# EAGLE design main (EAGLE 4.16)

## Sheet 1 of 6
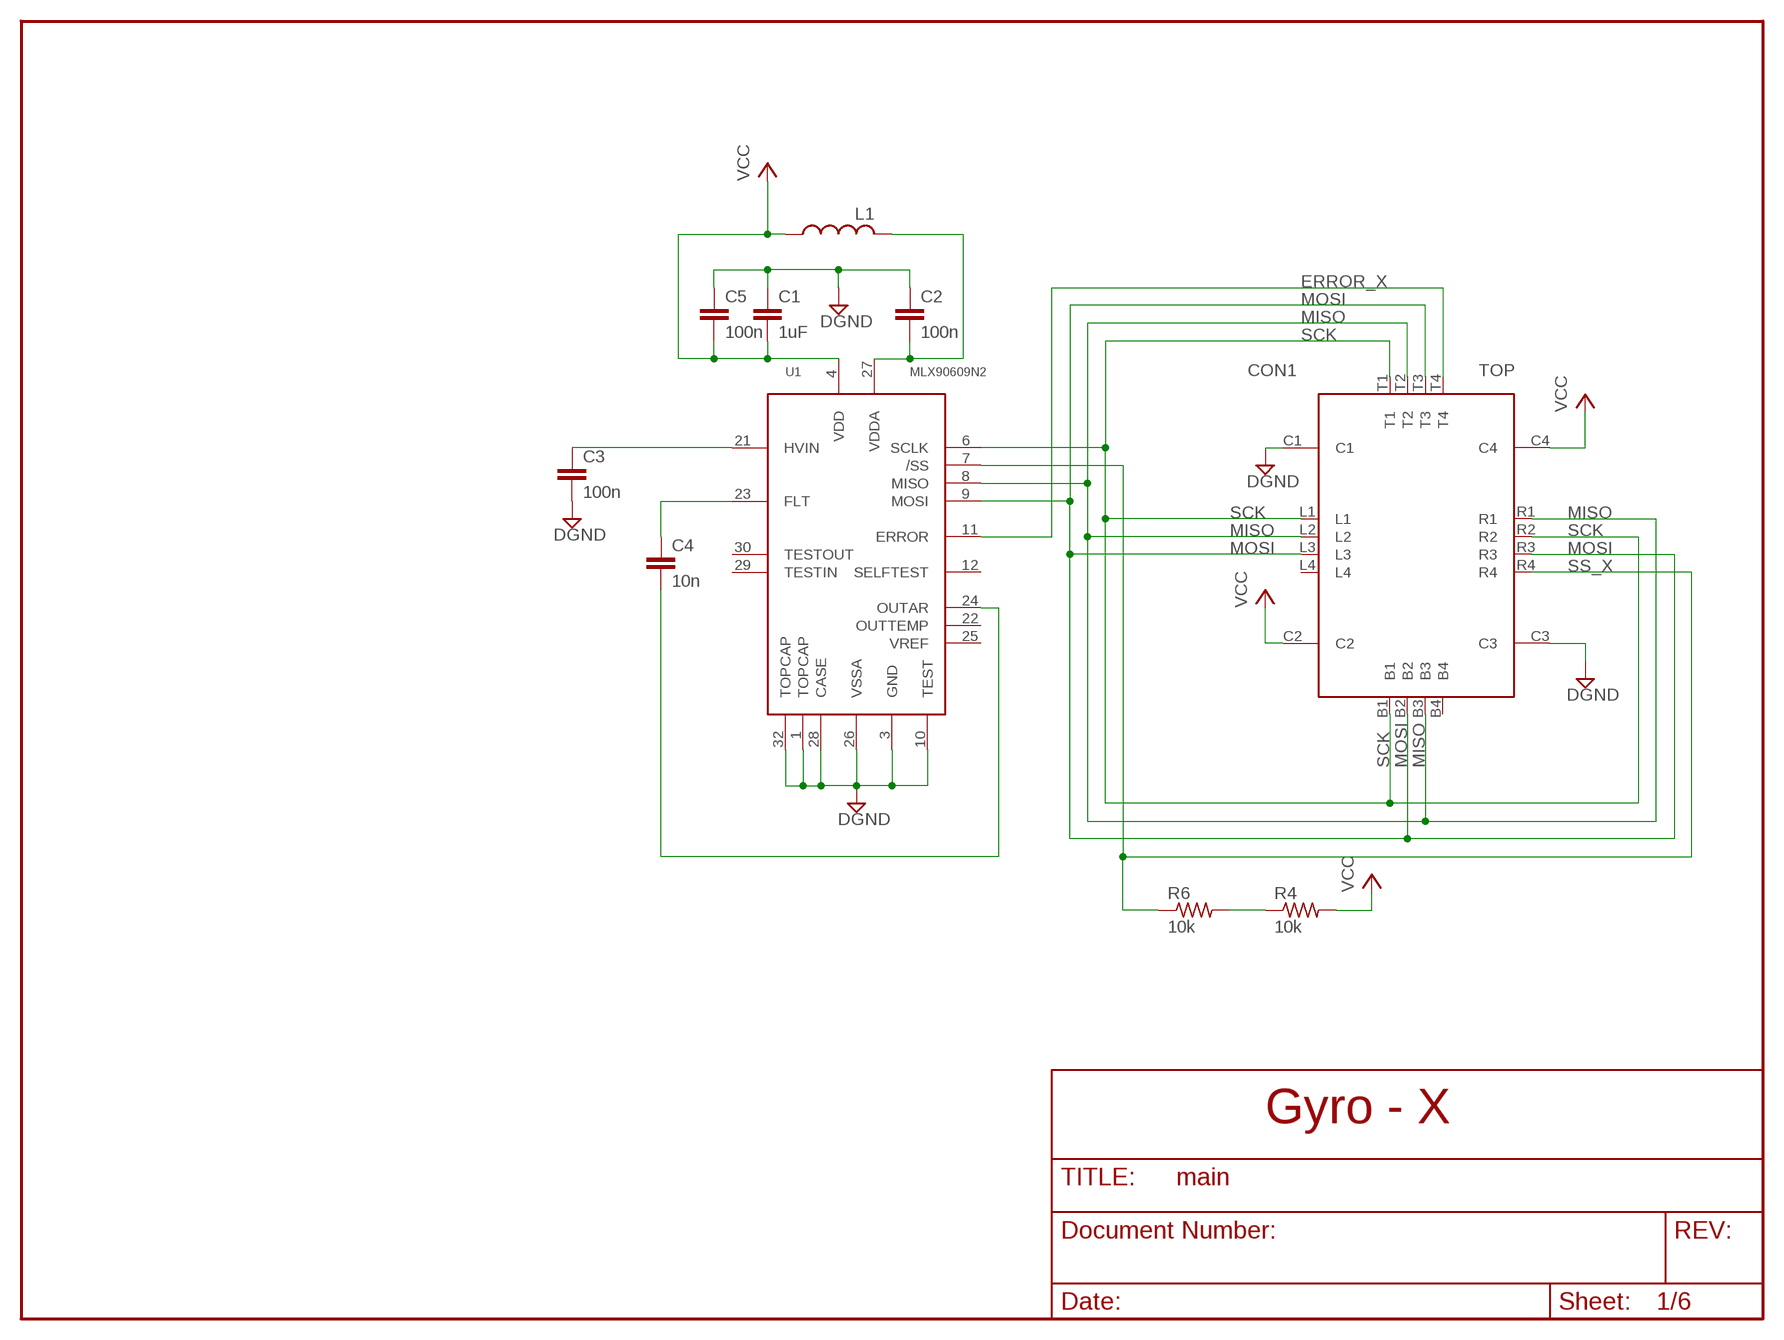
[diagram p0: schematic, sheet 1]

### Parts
C1  1uF  C-EUC0603  [C0603]
C2  100n  C-EUC0603  [C0603]
C3  100n  C-EUC0603  [C0603]
C4  10n  C-EUC0603  [C0603]
C5  100n  C-EUC0603  [C0603]
CON1  TOP  BOARDLEVEL  [BOARDLEVEL]
L1  L-USL2012C  [L2012C]
R4  10k  R-US_R0603  [R0603]
R6  10k  R-US_R0603  [R0603]
U1  MLX90609N2  [CLCC-32]

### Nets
DGND: C1.1 C2.1 C3.2 C5.1 CON1.C1 CON1.C3 U1.1(TOPCAP) U1.3(GND) U1.10(TEST) U1.26(VSSA) U1.28(CASE) U1.32(TOPCAP) ; also sheet 2,3,4,5,6
ERROR_X: CON1.T4 U1.11(ERROR) ; also sheet 4,5
MISO: CON1.B3 CON1.L2 CON1.R1 CON1.T2 U1.8(MISO) ; also sheet 2,3,4,5
MOSI: CON1.B2 CON1.L3 CON1.R3 CON1.T3 U1.9(MOSI) ; also sheet 2,3,4,5
N$3: C3.1 U1.21(HVIN)
N$4: C4.1 U1.23(FLT)
N$5: C4.2 U1.24(OUTAR)
N$11: R4.1 R6.2
N$14: C2.2 L1.2 U1.27(VDDA)
SCK: CON1.B1 CON1.L1 CON1.R2 CON1.T1 U1.6(SCLK) ; also sheet 2,3,4,5
SS_X: CON1.R4 R6.1 U1.7(/SS) ; also sheet 5
VCC: C1.2 C5.2 CON1.C2 CON1.C4 L1.1 R4.2 U1.4(VDD) ; also sheet 2,3,4,5,6
Unconnected: CON1.B4 CON1.L4 U1.12(SELFTEST) U1.22(OUTTEMP) U1.25(VREF) U1.29(TESTIN) U1.30(TESTOUT)

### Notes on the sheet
- Gyro - X

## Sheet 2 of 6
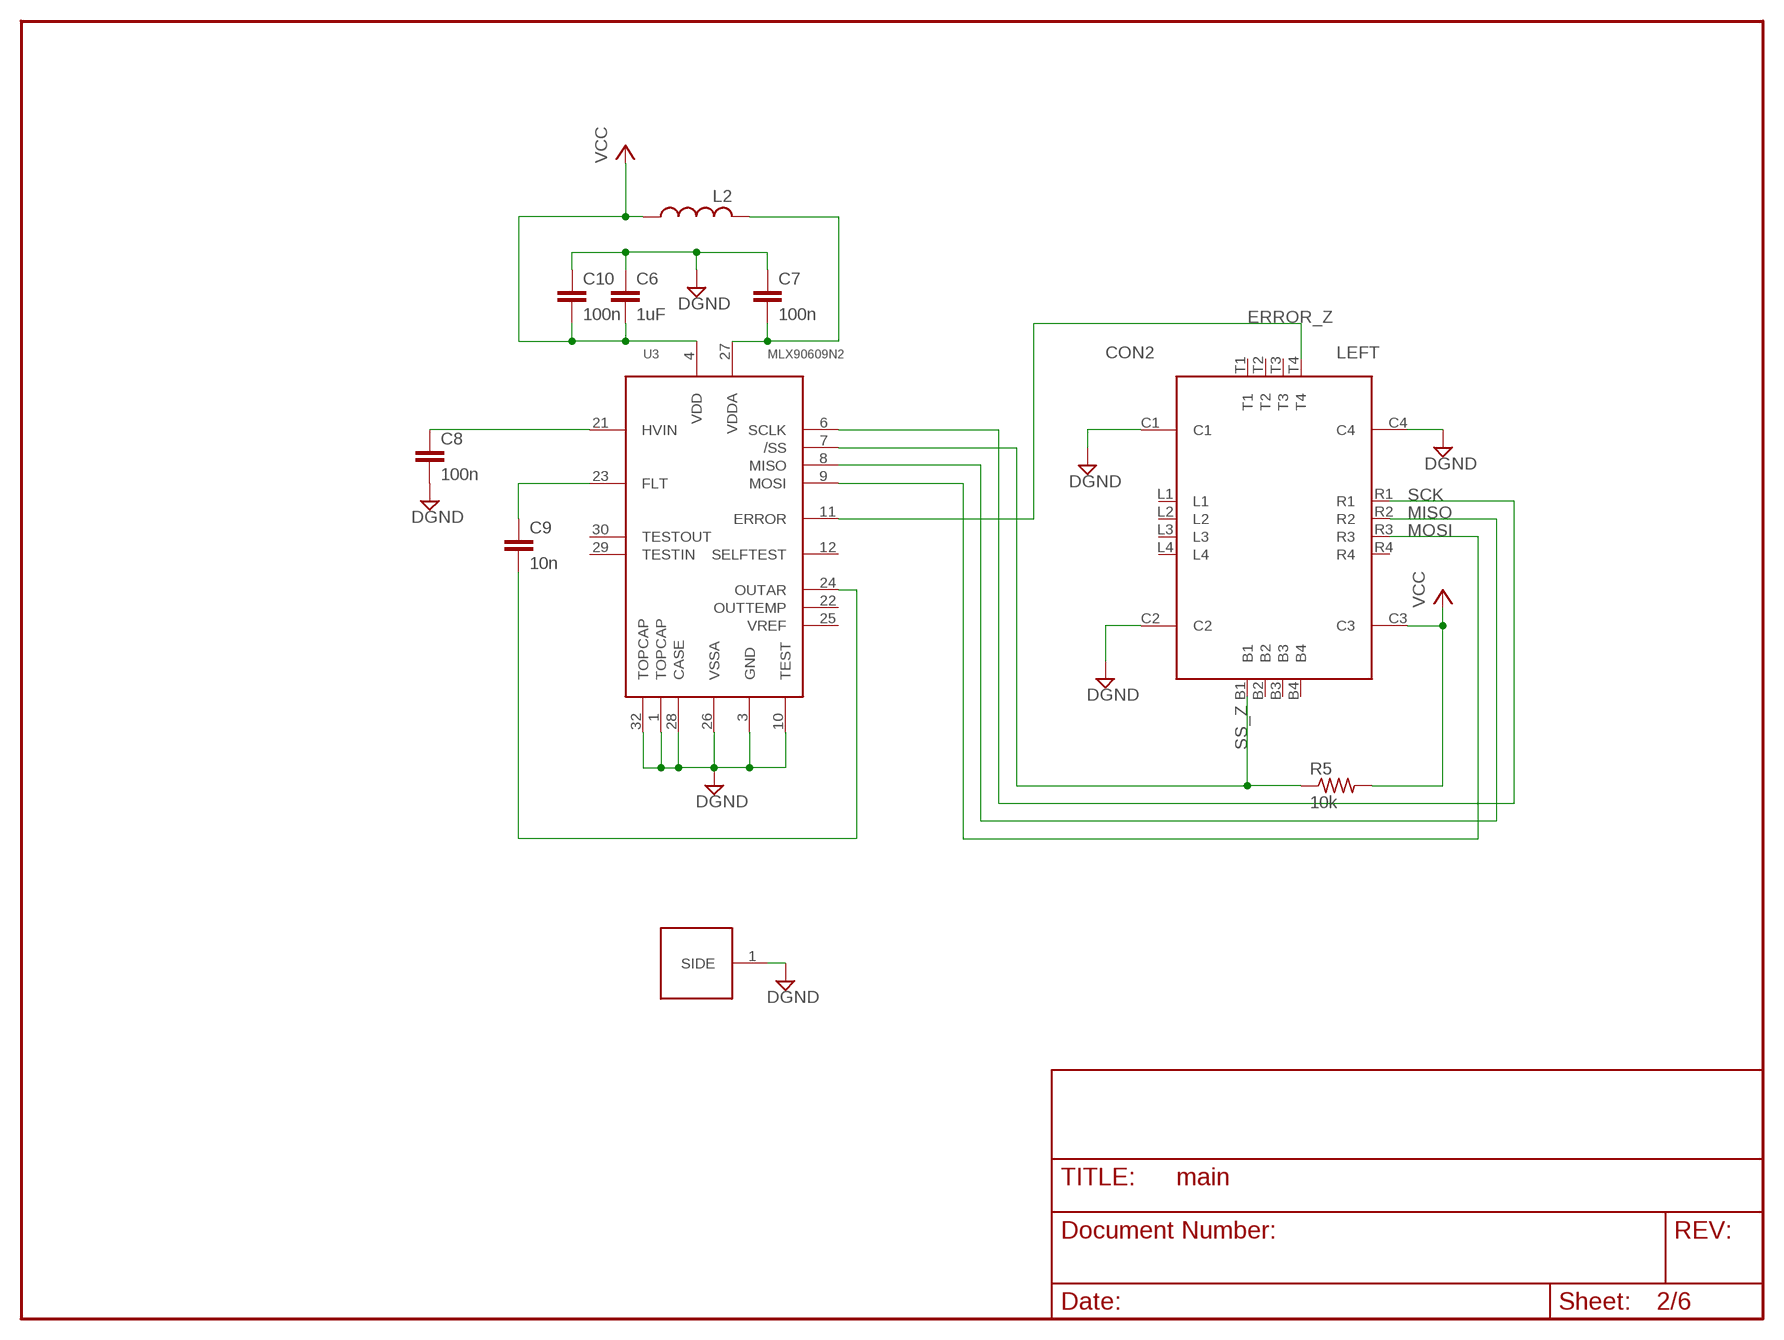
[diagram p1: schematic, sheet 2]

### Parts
C6  1uF  C-EUC0603  [C0603]
C7  100n  C-EUC0603  [C0603]
C8  100n  C-EUC0603  [C0603]
C9  10n  C-EUC0603  [C0603]
C10  100n  C-EUC0603  [C0603]
CON2  LEFT  BOARDLEVEL  [BOARDLEVEL]
L2  L-USL2012C  [L2012C]
R5  10k  R-US_R0603  [R0603]
U3  MLX90609N2  [CLCC-32]
U$1  1-SIDE  [1-SIDE]

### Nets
DGND: C6.1 C7.1 C8.2 C10.1 CON2.C1 CON2.C2 CON2.C4 U3.1(TOPCAP) U3.3(GND) U3.10(TEST) U3.26(VSSA) U3.28(CASE) U3.32(TOPCAP) U$1.1(SIDE) ; also sheet 1,3,4,5,6
ERROR_Z: CON2.T4 U3.11(ERROR) ; also sheet 4,5
MISO: CON2.R2 U3.8(MISO) ; also sheet 1,3,4,5
MOSI: CON2.R3 U3.9(MOSI) ; also sheet 1,3,4,5
N$12: C8.1 U3.21(HVIN)
N$13: C9.1 U3.23(FLT)
N$16: C9.2 U3.24(OUTAR)
N$54: C7.2 L2.2 U3.27(VDDA)
SCK: CON2.R1 U3.6(SCLK) ; also sheet 1,3,4,5
SS_Z: CON2.B1 R5.1 U3.7(/SS) ; also sheet 3,5
VCC: C6.2 C10.2 CON2.C3 L2.1 R5.2 U3.4(VDD) ; also sheet 1,3,4,5,6
Unconnected: CON2.B2 CON2.B3 CON2.B4 CON2.L1 CON2.L2 CON2.L3 CON2.L4 CON2.R4 CON2.T1 CON2.T2 CON2.T3 U3.12(SELFTEST) U3.22(OUTTEMP) U3.25(VREF) U3.29(TESTIN) U3.30(TESTOUT)

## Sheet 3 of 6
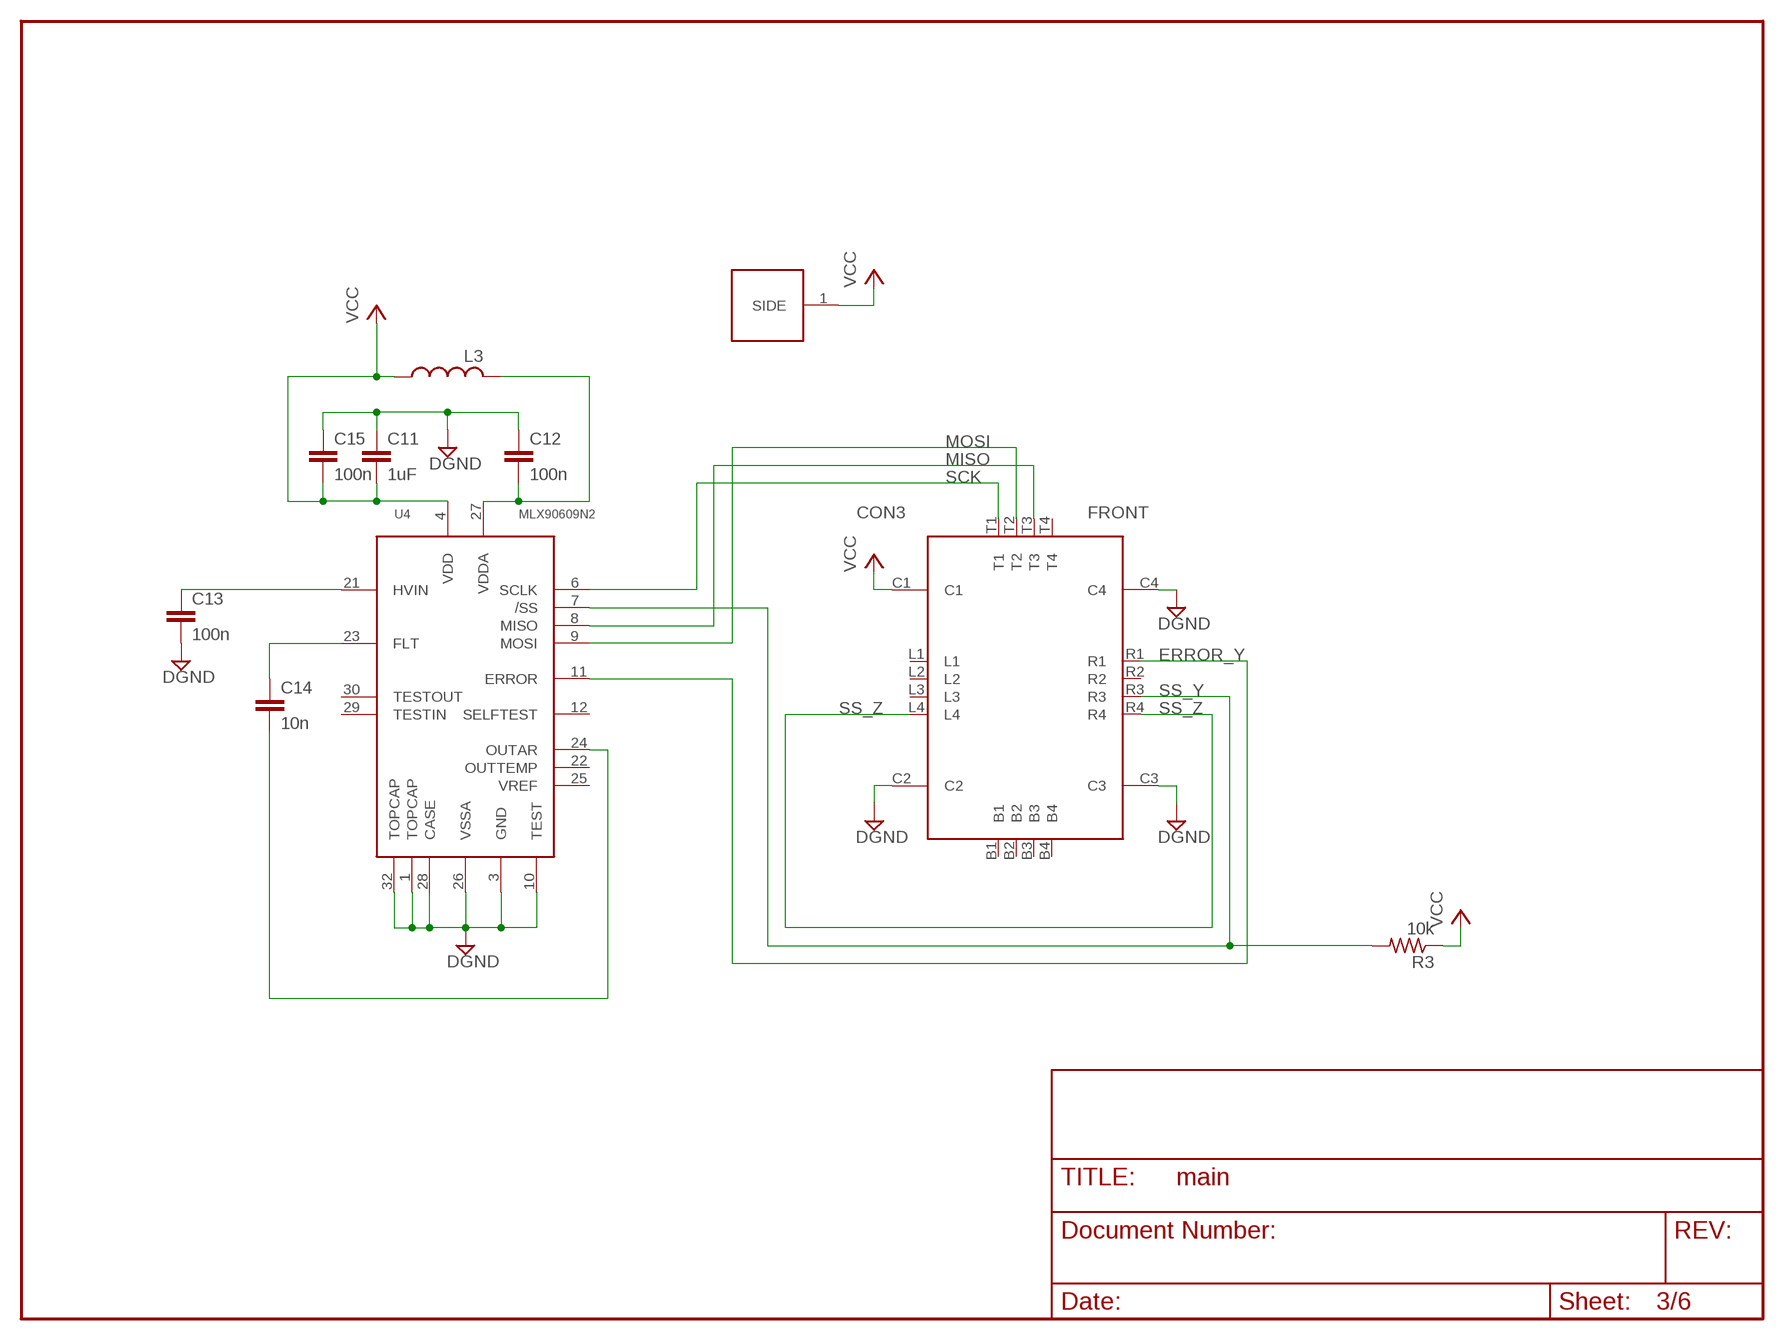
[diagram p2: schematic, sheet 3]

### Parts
C11  1uF  C-EUC0603  [C0603]
C12  100n  C-EUC0603  [C0603]
C13  100n  C-EUC0603  [C0603]
C14  10n  C-EUC0603  [C0603]
C15  100n  C-EUC0603  [C0603]
CON3  FRONT  BOARDLEVEL  [BOARDLEVEL]
L3  L-USL2012C  [L2012C]
R3  10k  R-US_R0603  [R0603]
U4  MLX90609N2  [CLCC-32]
U$4  1-SIDE  [1-SIDE]

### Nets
DGND: C11.1 C12.1 C13.2 C15.1 CON3.C2 CON3.C3 CON3.C4 U4.1(TOPCAP) U4.3(GND) U4.10(TEST) U4.26(VSSA) U4.28(CASE) U4.32(TOPCAP) ; also sheet 1,2,4,5,6
ERROR_Y: CON3.R1 U4.11(ERROR) ; also sheet 5
MISO: CON3.T3 U4.8(MISO) ; also sheet 1,2,4,5
MOSI: CON3.T2 U4.9(MOSI) ; also sheet 1,2,4,5
N$23: C13.1 U4.21(HVIN)
N$24: C14.1 U4.23(FLT)
N$26: C12.2 L3.2 U4.27(VDDA)
N$27: C14.2 U4.24(OUTAR)
SCK: CON3.T1 U4.6(SCLK) ; also sheet 1,2,4,5
SS_Y: CON3.R3 R3.2 U4.7(/SS) ; also sheet 5
SS_Z: CON3.L4 CON3.R4 ; also sheet 2,5
VCC: C11.2 C15.2 CON3.C1 L3.1 R3.1 U4.4(VDD) U$4.1(SIDE) ; also sheet 1,2,4,5,6
Unconnected: CON3.B1 CON3.B2 CON3.B3 CON3.B4 CON3.L1 CON3.L2 CON3.L3 CON3.R2 CON3.T4 U4.12(SELFTEST) U4.22(OUTTEMP) U4.25(VREF) U4.29(TESTIN) U4.30(TESTOUT)

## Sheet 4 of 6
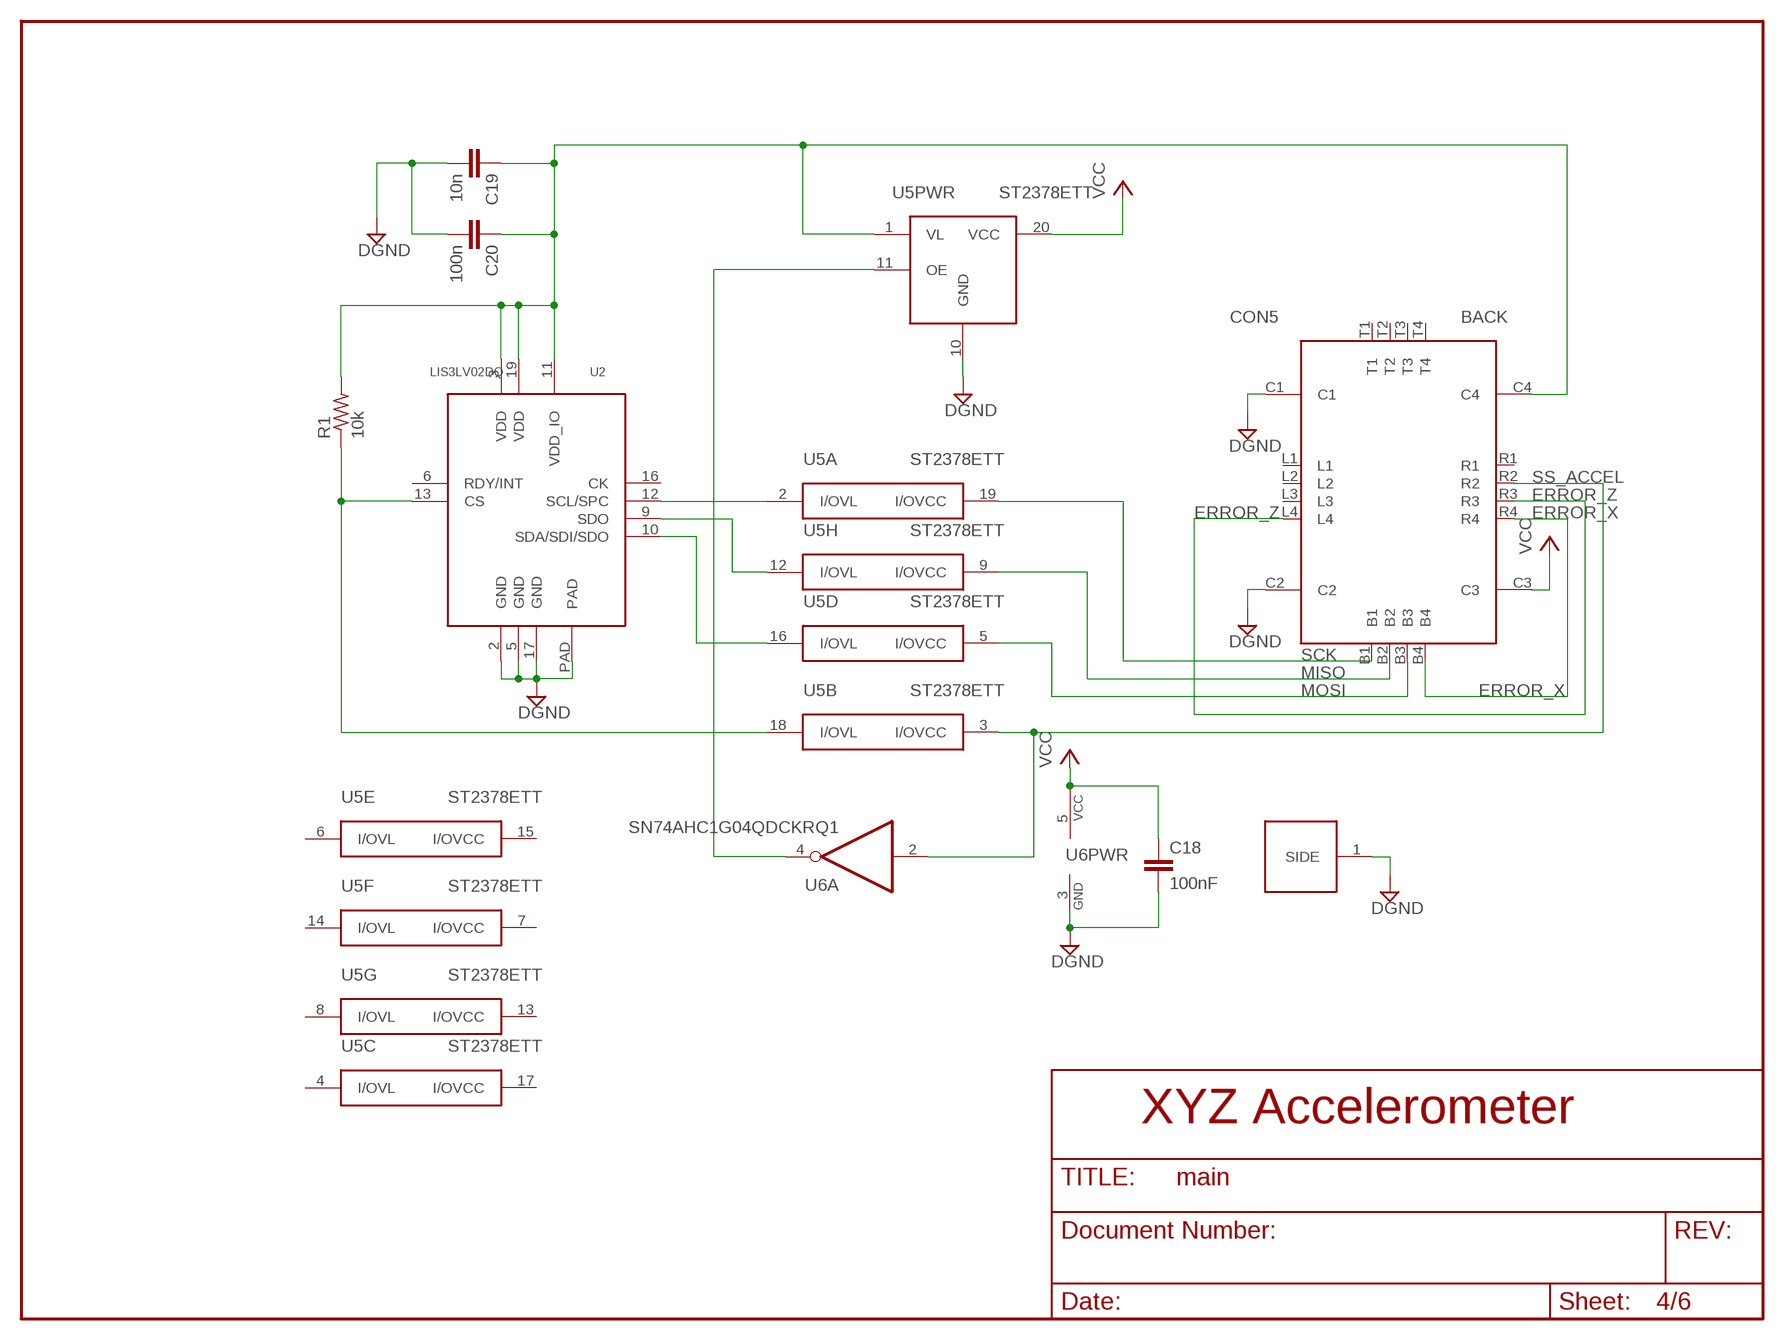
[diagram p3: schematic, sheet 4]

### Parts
C18  100nF  C-EUC0402  [C0402]
C19  10n  C-EUC0603  [C0603]
C20  100n  C-EUC0603  [C0603]
CON5  BACK  BOARDLEVEL  [BOARDLEVEL]
R1  10k  R-US_R0603  [R0603]
U2  LIS3LV02DQ  [QFPN-28]
U5  ST2378ETT  [TSSOP20]
U6  SN74AHC1G04QDCKRQ1  [SC70-5L]
U$3  1-SIDE  [1-SIDE]

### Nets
DGND: C18.2 C19.2 C20.2 CON5.C1 CON5.C2 U2.2(GND) U2.5(GND) U2.17(GND) U2.PAD U5.10(PWR:GND) U6.3(PWR:GND) U$3.1(SIDE) ; also sheet 1,2,3,5,6
ERROR_X: CON5.B4 CON5.R4 ; also sheet 1,5
ERROR_Z: CON5.L4 CON5.R3 ; also sheet 2,5
MISO: CON5.B2 U5.9(H:I/OVCC) ; also sheet 1,2,3,5
MOSI: CON5.B3 U5.5(D:I/OVCC) ; also sheet 1,2,3,5
N$8: U2.12(SCL/SPC) U5.2(A:I/OVL)
N$9: U2.10(SDA/SDI/SDO) U5.16(D:I/OVL)
N$10: U2.9(SDO) U5.12(H:I/OVL)
N$50: R1.1 U2.13(CS) U5.18(B:I/OVL)
N$53: U5.11(PWR:OE) U6.4(A:O)
SCK: CON5.B1 U5.19(A:I/OVCC) ; also sheet 1,2,3,5
SS_ACCEL: CON5.R2 U5.3(B:I/OVCC) U6.2(A:I) ; also sheet 5
VCC: C18.1 CON5.C3 U5.20(PWR:VCC) U6.5(PWR:VCC) ; also sheet 1,2,3,5,6
VCC2.5: C19.1 C20.1 CON5.C4 R1.2 U2.3(VDD) U2.11(VDD_IO) U2.19(VDD) U5.1(PWR:VL) ; also sheet 5
Unconnected: CON5.L1 CON5.L2 CON5.L3 CON5.R1 CON5.T1 CON5.T2 CON5.T3 CON5.T4 U2.6(RDY/INT) U2.16(CK) U5.4(C:I/OVL) U5.6(E:I/OVL) U5.7(F:I/OVCC) U5.8(G:I/OVL) U5.13(G:I/OVCC) U5.14(F:I/OVL) U5.15(E:I/OVCC) U5.17(C:I/OVCC)

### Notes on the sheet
- XYZ Accelerometer

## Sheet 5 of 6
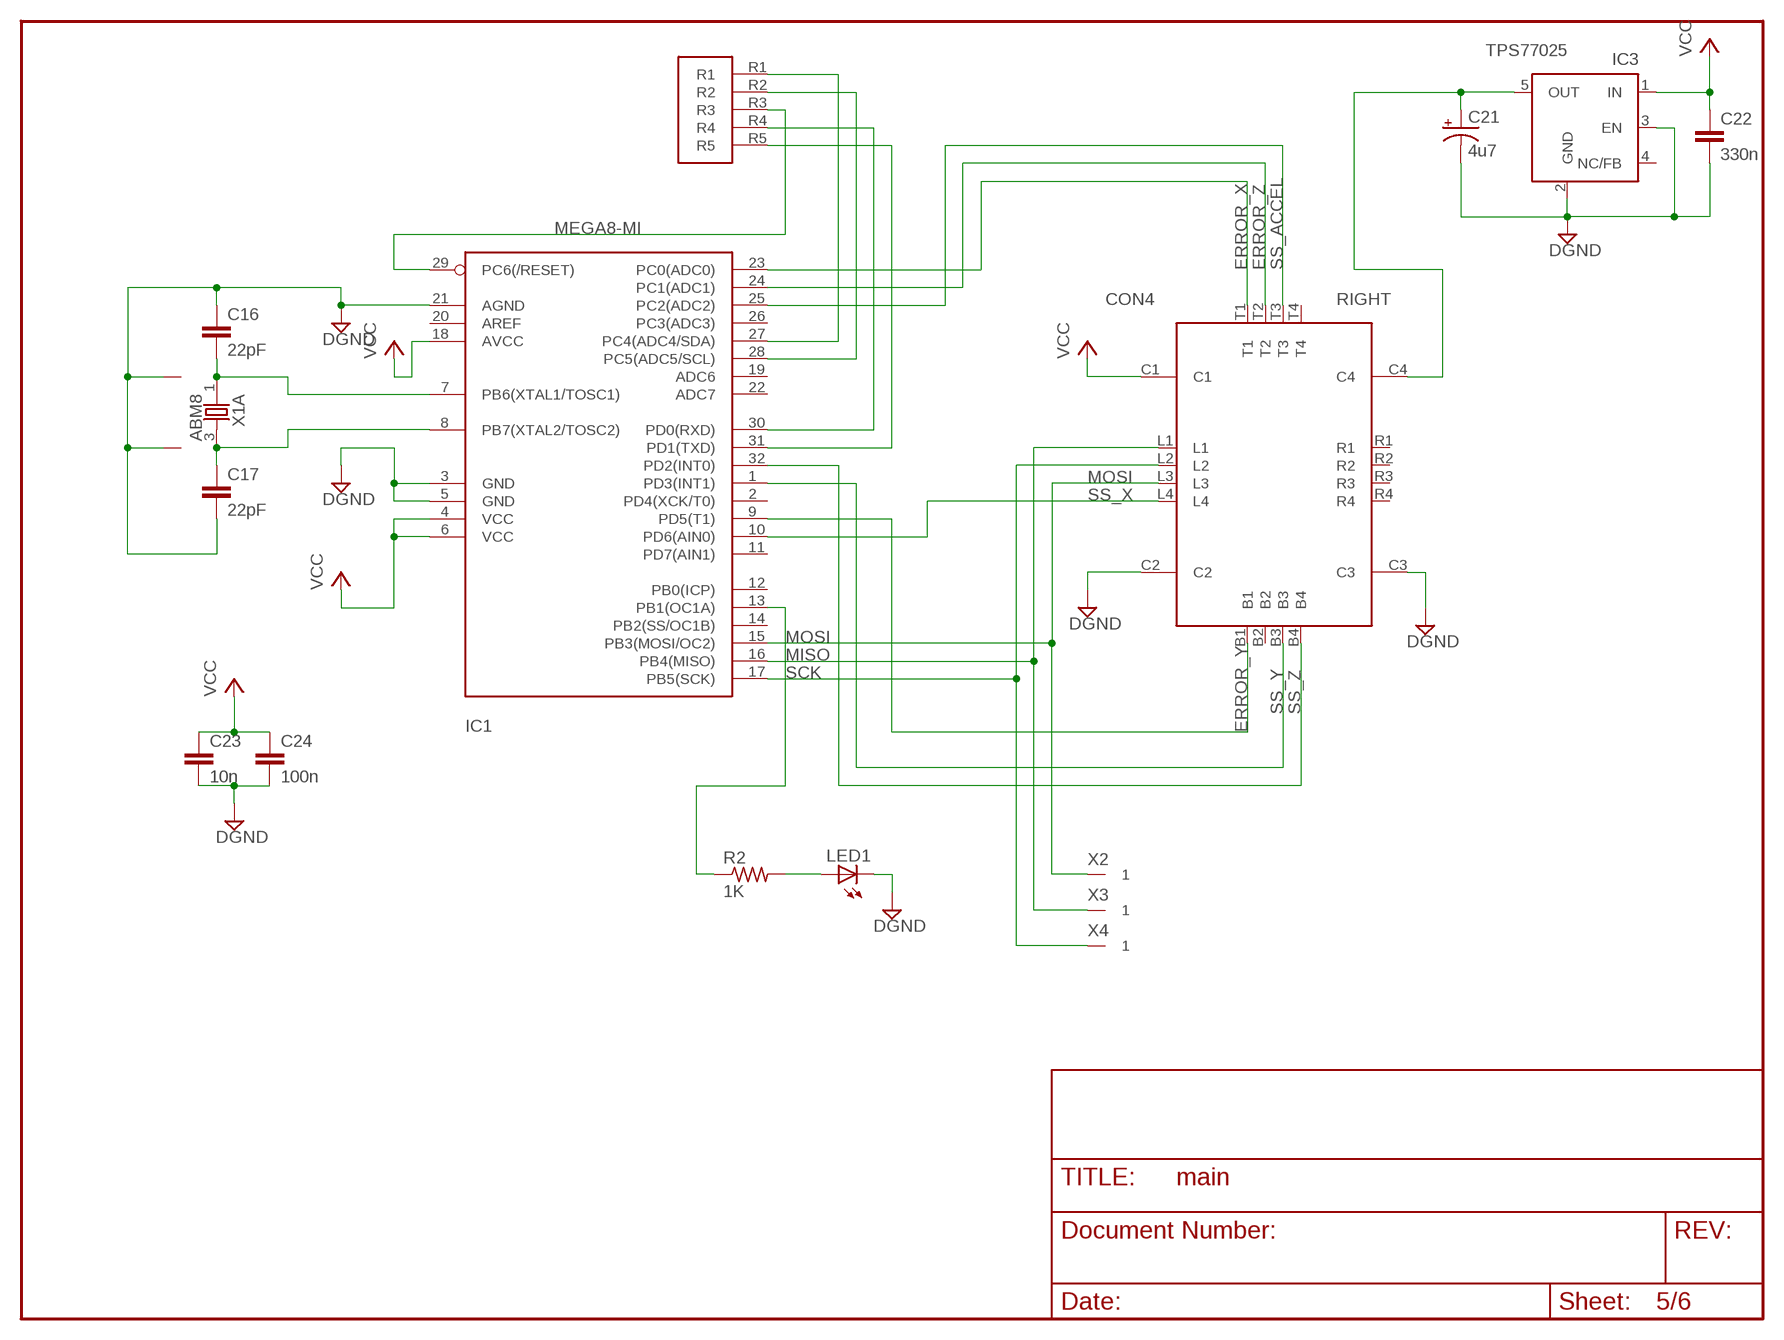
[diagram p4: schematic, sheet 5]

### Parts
C16  22pF  C-EUC0603  [C0603]
C17  22pF  C-EUC0603  [C0603]
C21  4u7  CPOL-USR/2012-12R  [R/2012-12R]
C22  330n  C-EUC0603  [C0603]
C23  10n  C-EUC0603  [C0603]
C24  100n  C-EUC0603  [C0603]
CON4  RIGHT  BOARDLEVEL  [BOARDLEVEL]
IC1  MEGA8-MI  [MLF32]
IC3  TPS77025  TPS770XX  [SOT23-5]
LED1  LEDCHIP-LED0805  [CHIP-LED0805]
R2  1K  R-US_R0603  [R0603]
U$2  5-RIGHT  [5-RIGHT]
X1  ABM8  [ABM8]
X2  ELLIPTICAL-PADS  [SMD-ELLIPSE]
X3  ELLIPTICAL-PADS  [SMD-ELLIPSE]
X4  ELLIPTICAL-PADS  [SMD-ELLIPSE]

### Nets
DGND: C16.1 C17.2 C21.- C22.2 C23.2 C24.2 CON4.C2 CON4.C3 IC1.3(GND) IC1.5(GND) IC1.21(AGND) IC3.2(GND) IC3.3(EN) LED1.C X1.2(GND) X1.4(GND) ; also sheet 1,2,3,4,6
ERROR_X: CON4.T1 IC1.23(PC0(ADC0)) ; also sheet 1,4
ERROR_Y: CON4.B1 IC1.9(PD5(T1)) ; also sheet 3
ERROR_Z: CON4.T2 IC1.24(PC1(ADC1)) ; also sheet 2,4
MISO: CON4.L1 IC1.16(PB4(MISO)) X3.1 ; also sheet 1,2,3,4
MOSI: CON4.L3 IC1.15(PB3(MOSI/OC2)) X2.1 ; also sheet 1,2,3,4
N$1: LED1.A R2.2
N$2: IC1.30(PD0(RXD)) U$2.R4
N$6: IC1.31(PD1(TXD)) U$2.R5
N$7: IC1.13(PB1(OC1A)) R2.1
N$15: IC1.29(PC6(/RESET)) U$2.R3
N$25: IC1.27(PC4(ADC4/SDA)) U$2.R1
N$56: IC1.28(PC5(ADC5/SCL)) U$2.R2
N$57: C16.2 IC1.7(PB6(XTAL1/TOSC1)) X1.1
N$58: C17.1 IC1.8(PB7(XTAL2/TOSC2)) X1.3
SCK: CON4.L2 IC1.17(PB5(SCK)) X4.1 ; also sheet 1,2,3,4
SS_ACCEL: CON4.T3 IC1.25(PC2(ADC2)) ; also sheet 4
SS_X: CON4.L4 IC1.10(PD6(AIN0)) ; also sheet 1
SS_Y: CON4.B3 IC1.1(PD3(INT1)) ; also sheet 3
SS_Z: CON4.B4 IC1.32(PD2(INT0)) ; also sheet 2,3
VCC: C22.1 C23.1 C24.1 CON4.C1 IC1.4(VCC) IC1.6(VCC) IC1.18(AVCC) IC3.1(IN) ; also sheet 1,2,3,4,6
VCC2.5: C21.+ CON4.C4 IC3.5(OUT) ; also sheet 4
Unconnected: CON4.B2 CON4.R1 CON4.R2 CON4.R3 CON4.R4 CON4.T4 IC1.2(PD4(XCK/T0)) IC1.11(PD7(AIN1)) IC1.12(PB0(ICP)) IC1.14(PB2(SS/OC1B)) IC1.19(ADC6) IC1.20(AREF) IC1.22(ADC7) IC1.26(PC3(ADC3)) IC3.4(NC/FB)

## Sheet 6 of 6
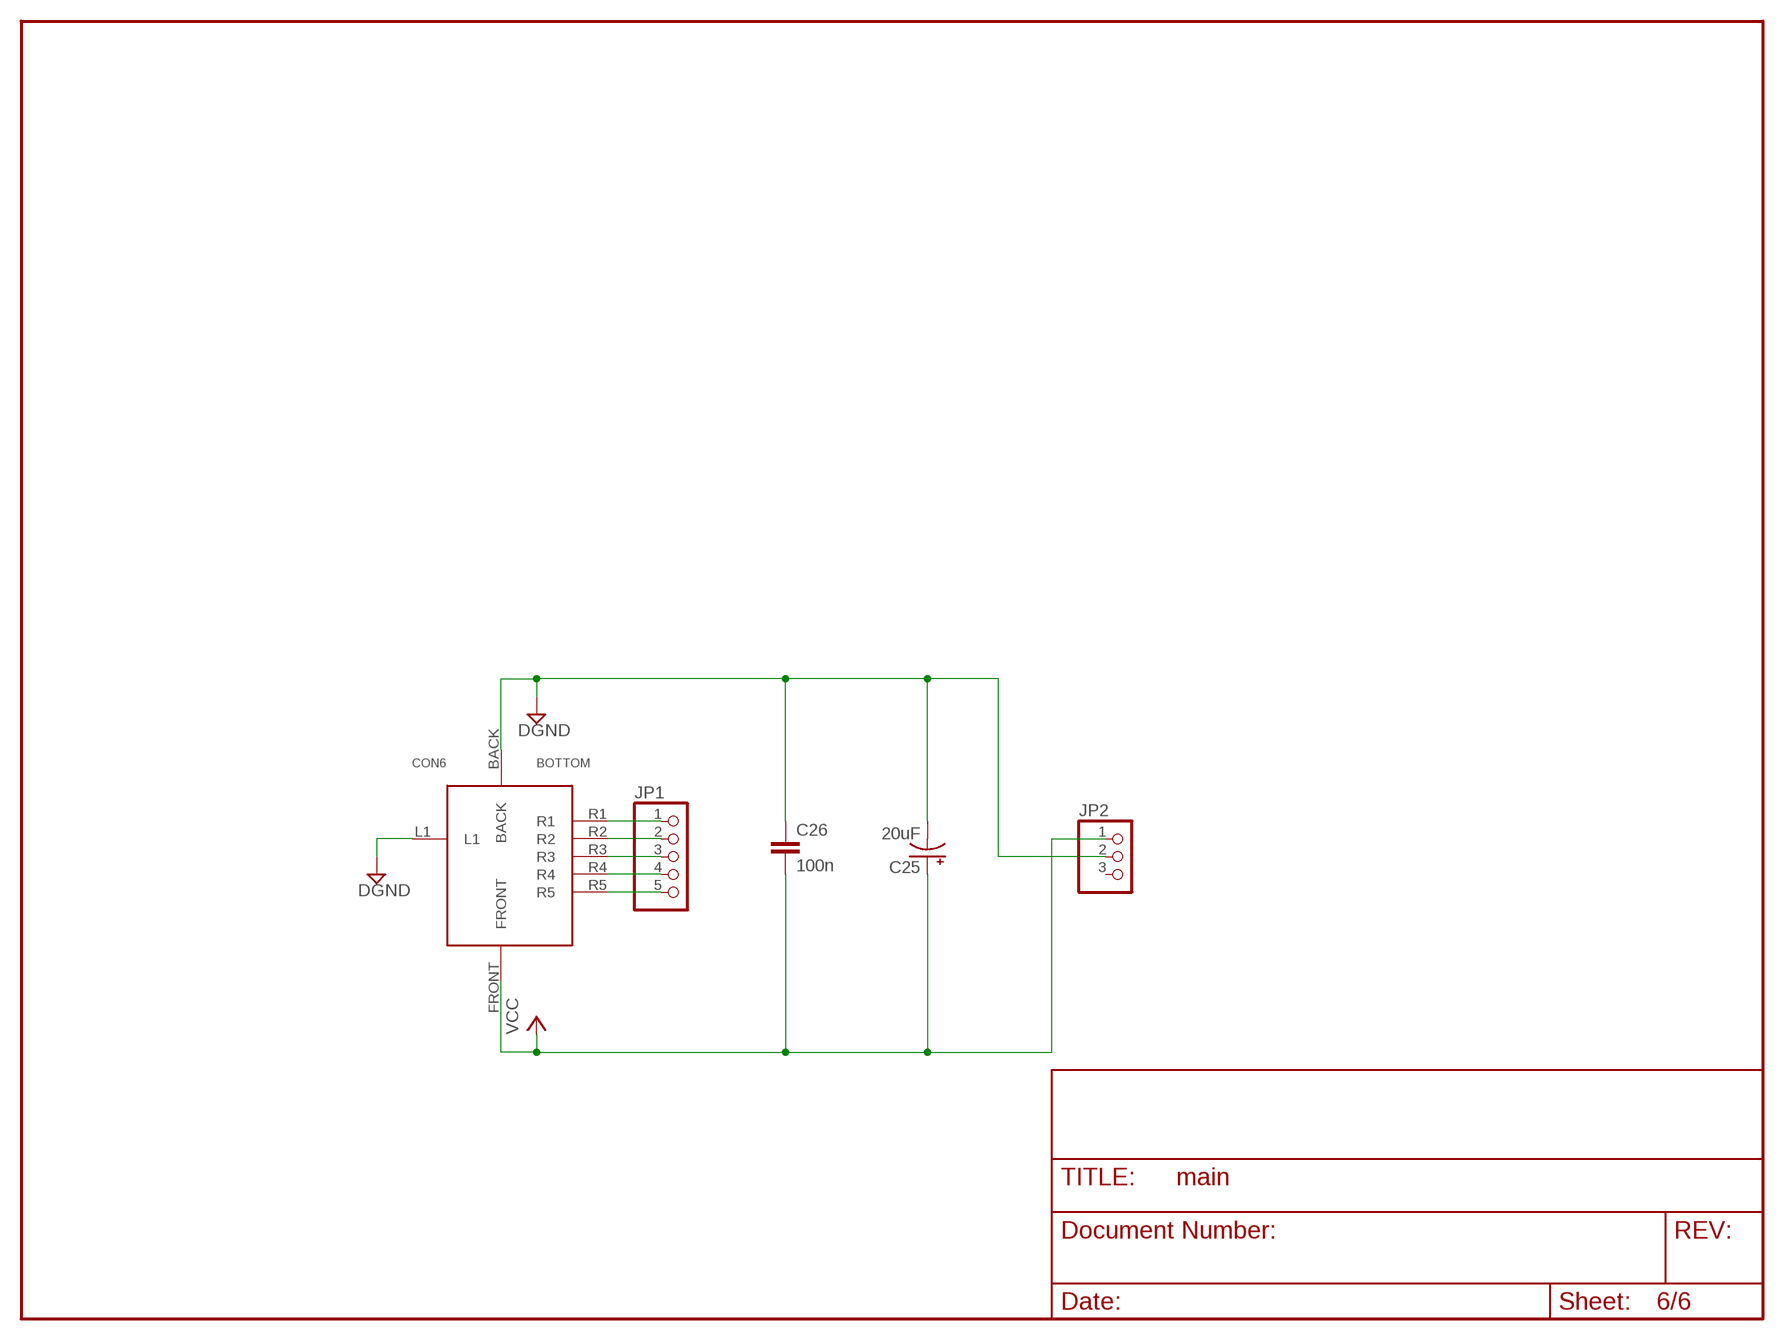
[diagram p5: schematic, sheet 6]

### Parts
C25  20uF  CPOL-USCT6032  [CT6032]
C26  100n  C-EUC0805  [C0805]
CON6  BOTTOM  [BOTTOM]
JP1  PINHD-1X5  [1X05]
JP2  PINHD-1X3  [1X03]

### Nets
DGND: C25.- C26.1 CON6.BACK CON6.L1 JP2.2 ; also sheet 1,2,3,4,5
N$61: CON6.R1 JP1.1
N$62: CON6.R2 JP1.2
N$63: CON6.R3 JP1.3
N$64: CON6.R4 JP1.4
N$65: CON6.R5 JP1.5
VCC: C25.+ C26.2 CON6.FRONT JP2.1 ; also sheet 1,2,3,4,5
Unconnected: JP2.3

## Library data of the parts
C1-C20 C22-C24 C26 = rcl:C-EU: CAPACITOR, European symbol
C21 C25 = rcl:CPOL-US: POLARIZED CAPACITOR, American symbol
CON1-CON5 = board-boardimu:BOARDLEVEL
CON6 = board-boardimu:BOTTOM
IC1 = atmel:MEGA8: MICROCONTROLLER 8 Kbytes FLASH 1 kbytes SRAM 512 bytes EEPROM USART 6-channel 10 bit ADC 2-channel 8 bit ADC Source: avr.lbr
IC3 = v-reg:TPS770XX: VOLTAGE REGULATOR
JP1 = pinhead:PINHD-1X5: PIN HEADER
JP2 = pinhead:PINHD-1X3: PIN HEADER
L1-L3 = rcl:L-US: INDUCTOR, American symbol
LED1 = led:LED: LED
R1-R6 = rcl:R-US_: RESISTOR, American symbol
U1 U3 U4 = melexis:MLX90609: Melexis Gyroscope
U2 = freescale:LIS3LV02DQ
U5 = st-microelectronics:ST2378E
U6 = 74xx-us:SN74AHC1G04QDCKRQ1
U$1 U$3 U$4 = board-boardimu:1-SIDE
U$2 = board-boardimu:5-RIGHT
X1 = crystal:ABM8
X2-X4 = special-pad:ELLIPTICAL-PAD

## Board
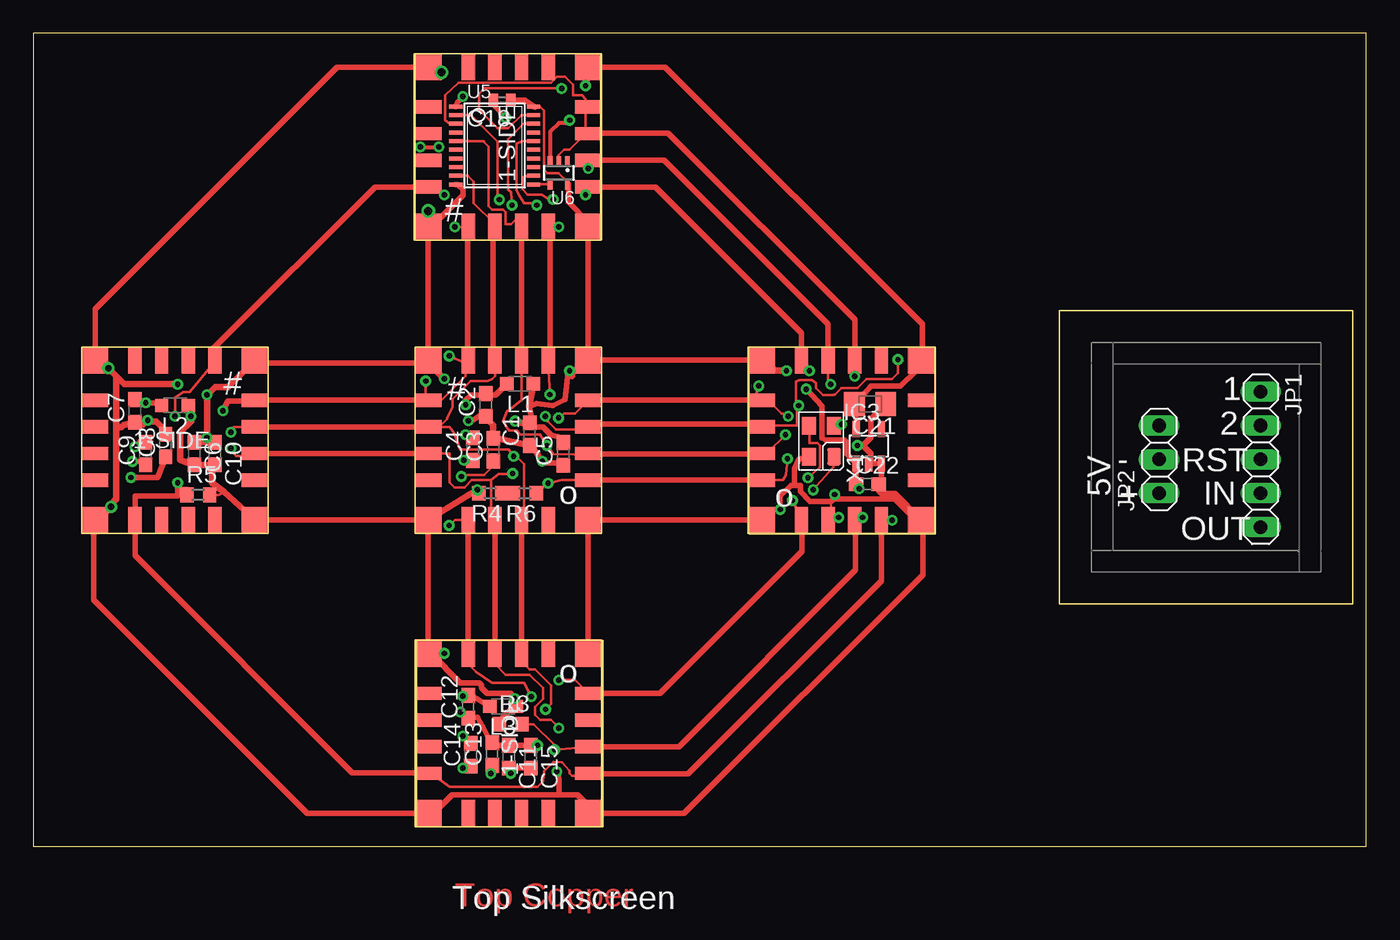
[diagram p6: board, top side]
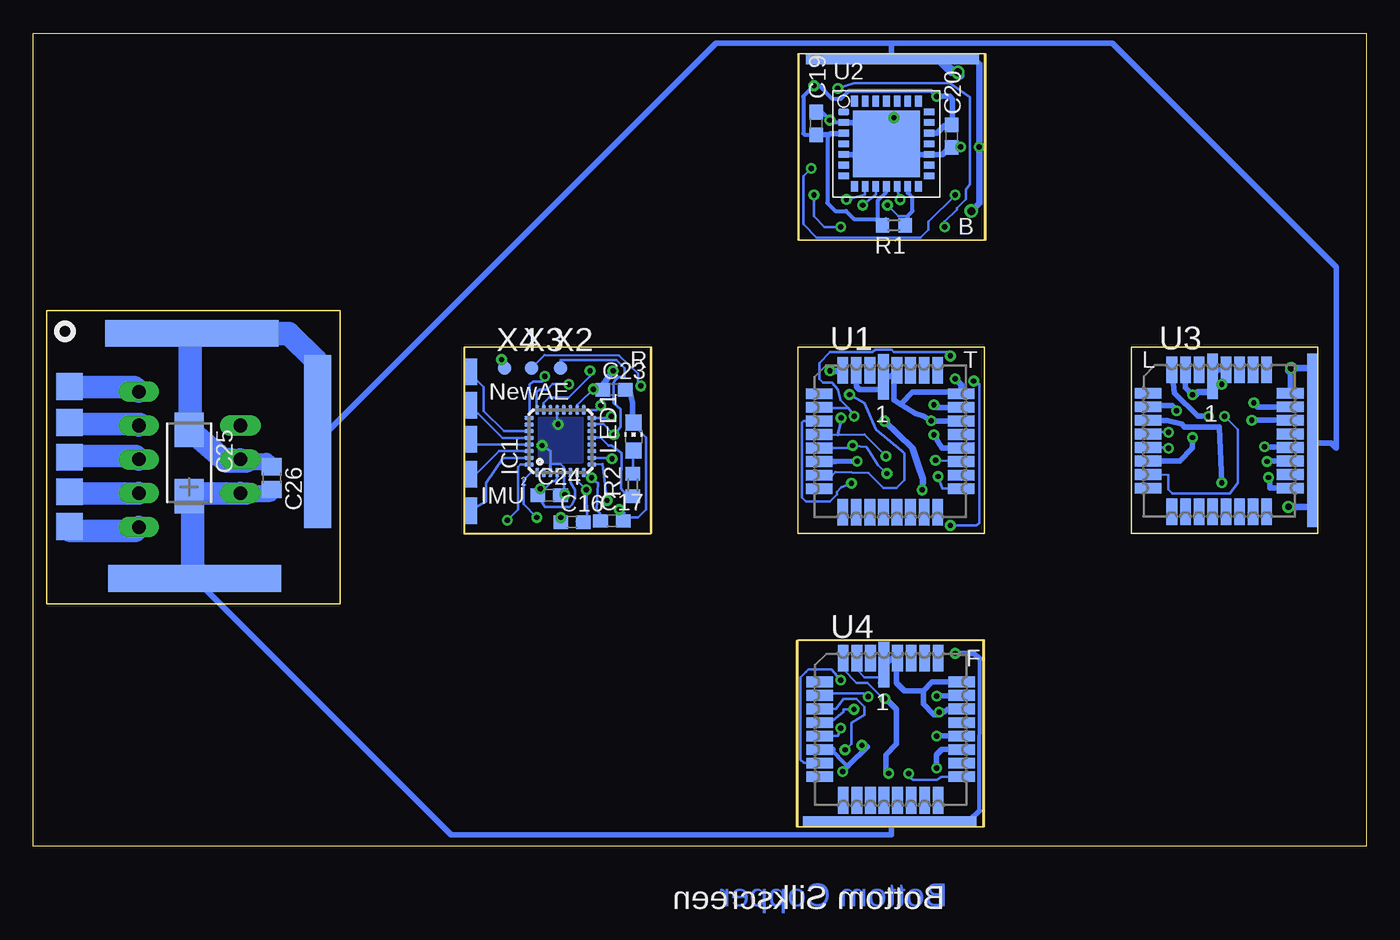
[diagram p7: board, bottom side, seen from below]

Size 100 x 61 mm. Coordinates in mm from the lower left corner, seen from the top.
Outline: 0,0 100,0 100,61 0,61 0,0
Copper layers (1*16): Top 0.035mm / dielectric 1.5mm / Bottom 0.035mm
Design rules "default": minimum track width 6mil, minimum drill 15mil, track to track 6mil, track to pad 6mil, pad to pad 6mil, via to via 6mil, smd to smd 0mil, copper to edge 0mil, drill to drill 6mil, minimum pad ring 10mil, minimum via ring 8mil, stop-mask expansion 4mil, vias tented up to drill 20mil, thermal gap 10mil

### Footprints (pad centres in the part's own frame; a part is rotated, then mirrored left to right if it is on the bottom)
C0603 = smd 1.1 x 1: 1 -0.85,0; 2 0.85,0
C0402 = smd 0.7 x 0.9: 1 -0.65,0; 2 0.65,0
R/2012-12R = smd 1.55 x 1.8: + 1.175,0; - -1.175,0
CT6032 = smd 2.6 x 2.2: + 2.5,0; - -2.5,0
C0805 = smd 1.3 x 1.5: 1 -0.85,0; 2 0.85,0
BOARDLEVEL = smd 1 x 2: B1 -3,-6; B2 -1,-6; B3 1,-6; B4 3,-6; T1 -3,6; T2 -1,6; T3 1,6; T4 3,6 | smd 2 x 2: C1 -6,6; C2 -6,-6; C3 6,-6; C4 6,6 | smd 2 x 1: L1 -6,3; L2 -6,1; L3 -6,-1; L4 -6,-3; R1 6,3; R2 6,1; R3 6,-1; R4 6,-3
BOTTOM = smd 13 x 2 bottom: BACK 0.1,9.3; FRONT -0.1,-9.1 | smd 2 x 13 bottom: L1 -9.315,1.17 | smd 2 x 2 bottom: R1 9.3,5.3; R2 9.3,2.6; R3 9.3,0; R4 9.3,-2.6; R5 9.3,-5.2
MLF32 = smd 0.7 x 0.3: 1 -2.35,1.75; 2 -2.35,1.25; 3 -2.35,0.75; 4 -2.35,0.25; 5 -2.35,-0.25; 6 -2.35,-0.75; 7 -2.35,-1.25; 8 -2.35,-1.75; 17 2.35,-1.75; 18 2.35,-1.25; 19 2.35,-0.75; 20 2.35,-0.25; 21 2.35,0.25; 22 2.35,0.75; 23 2.35,1.25; 24 2.35,1.75 | smd 0.3 x 0.7: 9 -1.75,-2.35; 10 -1.25,-2.35; 11 -0.75,-2.35; 12 -0.25,-2.35; 13 0.25,-2.35; 14 0.75,-2.35; 15 1.25,-2.35; 16 1.75,-2.35; 25 1.75,2.35; 26 1.25,2.35; 27 0.75,2.35; 28 0.25,2.35; 29 -0.25,2.35; 30 -0.75,2.35; 31 -1.25,2.35; 32 -1.75,2.35
SOT23-5 = smd 0.55 x 1.2: 1 -0.95,-1.3; 2 0,-1.3; 3 0.95,-1.3; 4 0.95,1.3; 5 -0.95,1.3
1X05 = drill 1.016 long: 1 -5.08,0; 2 -2.54,0; 3 0,0; 4 2.54,0; 5 5.08,0
1X03 = drill 1.016 long: 1 -2.54,0; 2 0,0; 3 2.54,0
L2012C = smd 1 x 1: 1 -1,0; 2 1,0
CHIP-LED0805 = smd 1.2 x 1.2: A 0,-1.05; C 0,1.05
R0603 = smd 1 x 1.1: 1 -0.85,0; 2 0.85,0
CLCC-32 = smd 0.8 x 3.4: 1 0,5.354 | smd 0.8 x 2: 2 -1.016,5.842; 3 -2.032,5.842; 4 -3.048,5.842; 13 -3.048,-4.826; 14 -2.032,-4.826; 15 -1.016,-4.826; 16 0,-4.826; 17 1.016,-4.826; 18 2.032,-4.826; 19 3.048,-4.826; 20 4.064,-4.826; 29 4.064,5.842; 30 3.048,5.842; 31 2.032,5.842; 32 1.016,5.842 | smd 2 x 0.8: 5 -4.826,4.064; 6 -4.826,3.048; 7 -4.826,2.032; 8 -4.826,1.016; 9 -4.826,0; 10 -4.826,-1.016; 11 -4.826,-2.032; 12 -4.826,-3.048; 21 5.842,-3.048; 22 5.842,-2.032; 23 5.842,-1.016; 24 5.842,0; 25 5.842,1.016; 26 5.842,2.032; 27 5.842,3.048; 28 5.842,4.064
QFPN-28 = smd 0.8 x 0.5: 1 -4.8,6.4; 2 -4.8,5.6; 3 -4.8,4.8; 4 -4.8,4; 5 -4.8,3.2; 6 -4.8,2.4; 7 -4.8,1.6; 15 1.6,1.6; 16 1.6,2.4; 17 1.6,3.2; 18 1.6,4; 19 1.6,4.8; 20 1.6,5.6; 21 1.6,6.4 | smd 0.5 x 0.8: 8 -4,0.8; 9 -3.2,0.8; 10 -2.4,0.8; 11 -1.6,0.8; 12 -0.8,0.8; 13 0,0.8; 14 0.8,0.8; 22 0.8,7.2; 23 0,7.2; 24 -0.8,7.2; 25 -1.6,7.2; 26 -2.4,7.2; 27 -3.2,7.2; 28 -4,7.2 | smd 5 x 5: PAD -1.6,4
TSSOP20 = smd 0.305 x 0.991: 1 -2.925,-2.918; 2 -2.275,-2.918; 3 -1.625,-2.918; 4 -0.975,-2.918; 5 -0.325,-2.918; 6 0.325,-2.918; 7 0.975,-2.918; 8 1.625,-2.918; 9 2.275,-2.918; 10 2.925,-2.918; 11 2.925,2.918; 12 2.275,2.918; 13 1.625,2.918; 14 0.975,2.918; 15 0.325,2.918; 16 -0.325,2.918; 17 -0.975,2.918; 18 -1.625,2.918; 19 -2.275,2.918; 20 -2.925,2.918
SC70-5L = smd 0.35 x 0.8: 1 -0.65,-0.85; 2 0,-0.85; 3 0.65,-0.85; 4 0.65,0.85; 5 -0.65,0.85
1-SIDE = smd 0.8 x 13 bottom: 1 -6.6,0
5-RIGHT = smd 1 x 2 bottom: R1 6.535,5.17; R2 6.535,2.64; R3 6.535,0.11; R4 6.535,-2.53; R5 6.535,-5.27
ABM8 = smd 1.321 x 1.041: 1 -2.311,0.432; 2 0,0.432; 3 0,2.311; 4 -2.311,2.311
SMD-ELLIPSE = smd 1 x 1: 1 0,0

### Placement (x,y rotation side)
C1  37.24,30.92 90 top
C2  33.95,33.12 90 top
C3  34.52,29.76 90 top
C4  32.98,29.79 90 top
C5  39.76,29.45 90 top
C6  12.08,29.47 270 top
C7  7.63,32.67 90 top
C8  9.93,30.07 90 top
C9  8.43,29.47 90 top
C10  13.63,29.47 270 top
C11  35.68,6.72 270 top
C12  32.63,10.47 90 top
C13  34.43,6.92 90 top
C14  32.83,6.87 90 top
C15  37.33,6.72 270 top
C16  59.58,24.32 0 bottom
C17  56.59,24.41 0 bottom
C18  35.17,56 180 top
C19  41.26,54.23 90 bottom
C20  31.11,53.28 270 bottom
C21  62.78,33.17 180 top
C22  62.58,27.17 0 top
C23  56.43,34.26 0 bottom
C24  61.3,26.33 0 bottom
C25  88.31,28.76 270 bottom
C26  82.11,27.62 270 bottom
CON1  35.63,30.47 0 top
CON2  10.63,30.47 0 top
CON3  35.63,8.47 0 top
CON4  60.63,30.47 0 top
CON5  35.63,52.47 0 top
CON6  87.99,29.2 0 top
IC1  60.45,30.39 90 bottom
IC3  62.68,30.02 0 top
JP1  92.09,29.03 270 top
JP2  84.47,29.03 90 top
L1  36.52,34.7 180 top
L2  10.63,33.07 180 top
L3  35.24,10.49 180 top
LED1  54.96,30.73 0 bottom
R1  35.44,46.6 180 bottom
R2  55.02,27.11 90 bottom
R3  35.82,9.16 0 top
R4  34.28,26.49 180 top
R5  12.38,26.36 0 top
R6  36.88,26.48 180 top
U1  36.22,29.88 0 bottom
U2  34.4,48.71 0 bottom
U3  11.53,29.92 0 bottom
U4  36.18,8.27 0 bottom
U5  34.61,52.58 270 top
U6  39.42,50.53 180 top
U$1  10.63,30.47 0 top
U$2  60.68,30.44 0 top
U$3  35.55,52.48 270 top
U$4  35.76,8.46 90 top
X1  60.51,31.55 90 top
X2  60.43,35.87 0 bottom
X3  62.63,35.87 0 bottom
X4  64.63,35.87 0 bottom

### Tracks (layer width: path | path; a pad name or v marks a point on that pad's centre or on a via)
DGND  (via drill 0.4, 0.5, 0.6)
  Top 0.2: X1.2 60.15,31.55 60.23,31.47 60.43,31.67 v60.63,31.67 | v60.43,24.67 59.83,25.27 59.83,25.87 | v60.12,26.39 60.04,26.47 60.03,26.47 60.03,26.07
  Top 0.3: C18.2 34.52,55.58 v35.43,54.67 | v29.03,52.47 v30.43,52.47 | U6.3 38.77,53.61 39.43,54.27 40.03,54.27 v40.24,54.48
  Top 0.4: C7.1 8.23,31.62 v8.58,31.97 | v5.63,35.87 5.23,35.87 CON2.C1 | v32.63,31.92 32.83,31.87 33.43,32.27 C2.1 | 66.63,24.57 66.53,24.57 64.63,26.47 63.63,26.47 63.43,26.67 C22.2 63.43,27.07 63.63,27.27 IC3.3 IC3.2 | IC3.2 | IC3.2 62.63,28.67 | X1.4 58.23,29.27 57.43,29.07 57.11,28.31 57.11,27.07 | CON4.C2 55.43,25.27 v56.03,25.27 56.03,26.27 56.83,27.07 57.11,27.07 | 57.11,27.07 57.57,27.07 57.57,26.61 58.26,25.87 58.98,25.86 58.99,25.87 59.83,25.87 60.03,26.07 64.63,26.07 66.23,24.47 66.83,24.47 | 62.23,30.07 v61.83,30.07 | 62.23,30.07 62.83,29.47 62.83,28.87 IC3.2 | IC3.2 | 60.03,31.27 60.08,31.32 X1.2 | C21.- 63.96,33.2 62.83,32.07 62.83,30.67 62.23,30.07 | 29.63,47.07 30.03,47.07 | U5.10 31.85,49.66 32.23,49.27 32.23,48.87 29.83,46.47 CON5.C2 | v37.83,7.57 C15.1 35.93,7.57 35.83,7.67 35.73,7.57 C11.1 34.53,7.57 34.43,7.67 | 34.43,7.67 34.28,7.92 33.72,9.01 33.33,9.67 32.63,9.67 C12.1 32.48,9.62 v32.03,10.07 | CON3.C2 30.03,2.47 31.43,3.87 39.43,3.87 | 39.43,3.87 40.83,3.87 41.43,3.27 41.43,2.67 CON3.C3 41.83,2.27 | 39.43,3.87 39.43,5.07 v39.28,5.6 | C1.1 37.83,29.47 38.23,28.77 | C5.1 39.77,28.47 39.74,28.53 39.23,28.77 38.23,28.77 | v38.18,28.89 37.81,29.44 38.23,28.77 | 34.43,7.67 C13.2
  Top 0.406: CON1.C1 CON5.C2 | 4.68,36.27 4.63,36.32 CON2.C1 4.63,40.32 22.78,58.47 CON5.C1 v30.63,58.07 | CON3.C3 48.83,2.47 66.73,20.37 66.73,24.47 66.63,24.57 CON4.C3 | 41.43,24.47 41.38,24.52 | 41.43,24.47 CON1.C3 CON4.C2 | CON3.C4 41.63,24.27 41.43,24.47 | CON2.C4 16.43,36.27 29.63,36.27 | CON3.C2 20.53,2.47 4.53,18.47 4.53,23.92 4.68,24.07 4.63,24.12 CON2.C2
  Top 0.5: 16.43,36.27 14.63,34.47 13.63,34.47 v13.03,33.87 v13.03,30.67 13.03,30.32 | C8.2 10.03,31.07 9.23,31.87 8.63,31.87 8.58,31.92 v8.58,31.97 | C10.1 13.68,30.32 13.63,30.27 13.58,30.32 13.03,30.32 | 13.03,30.32 C6.1 12.43,30.47 | CON2.C1 5.03,36.47 6.23,35.27 | 6.23,35.27 6.83,34.67 v10.83,34.67 | C7.1 6.78,31.62 6.63,31.47 6.43,31.47 6.23,31.27 | 6.23,31.27 6.23,35.27 | 4.83,24.47 6.23,26.07 6.23,31.27 | CON2.C2 4.83,24.47 | 4.83,24.47 v5.83,25.47 | CON1.C1 29.63,36.27 v30.83,35.07 | CON5.C2 29.63,47.07 v29.63,47.67 | C2.1 33.95,32.18 34.51,31.6 C3.2 34.83,30.59 C1.1
  Bottom 0.2: C24.2 60.21,26.65 60.23,26.67 60.2,26.7 IC1.5 60.23,28.07 60.23,28.47 60.43,28.67 61.23,28.67 61.23,28.07 IC1.3 61.2,29.64 v61.83,30.07 | v60.63,31.67 60.83,31.67 60.7,31.8 IC1.21 | 60.58,24.32 C16.1 v60.43,24.67 | C24.2 60.05,26.65 | U4.3 38.21,13.25 37.63,12.67 36.63,12.67 36.23,13.07 | 55.03,31.67 54.03,30.67 54.03,25.27 54.63,24.67 55.83,24.67 55.83,24.5 C17.2 | C24.2 60.43,26.31 60.43,26.27 60.24,26.27 v60.12,26.39
  Bottom 0.3: v35.43,54.67 35.43,53.27 36.03,52.67 | C19.2 40.84,55.08 v40.24,54.48 40.07,54.31 U2.2 | C20.2 30.47,52.43 v30.43,52.47 | 40.01,7.25 40.01,7.12 39.6,6.71 39.6,6.68 38.91,6 38.9,6
  Bottom 0.4: U3.26 5.71,31.95 5.73,31.97 v8.58,31.97 | U3.28 5.69,35.81 v5.63,35.87 | 11.63,35.27 | 11.63,35.27 U3.1 | U3.32 11.14,35.76 11.63,35.27 | U3.3 13.56,34.4 v13.03,33.87 12.83,33.87 | 11.63,34.67 11.63,35.27 | U1.10 39.82,28.86 v38.18,28.89 | U1.32 35.2,35.7 35.43,35.47 | 35.43,35.47 35.67,35.23 U1.1 36.22,35.08 36.23,35.07 36.23,34.47 36.43,34.27 38.03,34.27 38.25,34.49 U1.3 | 35.43,35.47 35.43,33.47 34.91,33.14 | 34.91,33.14 33.83,32.47 33.23,32.27 v32.63,31.92 32.59,31.91 U1.26 | C23.2 55.26,34.3 55.03,33.27 55.03,31.87 55.01,31.69 | 55.03,31.67 55.01,31.69 | 55.01,31.69 LED1.C | C17.2 55.74,24.98 v56.03,25.27 | C20.2 31.19,52.43 31.23,52.47 31.79,51.91 U2.17 33.99,51.91 34.23,51.67 35.03,51.67 36.03,52.67 | U2.5 36.99,51.91 36.19,52.71 U2.PAD 36.03,52.67 | U2.2 37.67,54.31 36.03,52.67 | 30.63,10.27 30.83,10.27 30.8,10.3 U4.26 30.6,10.3 30.63,10.27 | 30.63,10.27 31.43,10.27 31.63,10.07 v32.03,10.07 32.03,9.87 32.43,9.87 33.23,10.67 33.23,11.67 | U4.28 32.57,12.33 33.23,11.67 | 33.23,11.67 34.63,11.67 35.23,12.27 35.23,13.87 35.43,14.07 35.39,14.11 U4.32 35.59,14.11 36.18,13.52 | 36.18,13.52 36.23,13.47 | 36.18,13.52 U4.1 36.23,13.67 36.23,13.07 36.23,12.47 36.43,12.27 | 41.03,7.27 U4.10 40.01,7.25 | v39.28,5.6 38.9,6 38.83,6.07 37.43,7.47 37.63,7.47 37.83,7.67 v37.83,7.57 | 13.23,30.67 v13.03,30.67 13.03,29.87 14,28.9 U3.10 | U1.28 30.5,34.07 34.03,34.07 34.83,33.27 34.83,33.22 34.91,33.14 | CON6.L1 48.77,60.27 35.63,60.27 | 35.63,60.27 19.03,60.27 2.23,43.47 2.23,29.87 2.63,30.27 4.03,30.27 U$1.1 | U$3.1 35.63,59.16 35.63,60.27
  Bottom 0.406: 87.01,38.5 CON6.BACK | U$3.1 32.24,59.08 31.63,58.47 | v30.63,58.07 31.63,58.47 | 31.63,58.47 31.15,57.99
  Bottom 0.5: U$1.1 4.03,35.87 v5.63,35.87 5.83,35.67 | v5.83,25.47 4.03,25.47 | U1.28 30.38,34.62 v30.83,35.07 | v29.63,47.67 29.03,48.27 v29.03,52.47 29.03,58.67 29.43,59.07 34.43,59.07 34.63,59.27 | 11.63,34.67 11.62,34.67 v10.83,34.67 | 12.83,33.87 12.63,34.07 11.63,34.07 11.03,34.67 v10.83,34.67 | v10.83,34.67 10.63,34.67
  Bottom 0.6: v30.63,58.07 30.43,57.82 31.93,58.92 31.93,58.87
  Bottom 1.27: C26.1 82.51,28.87 84.63,28.87 JP2.2
  Bottom 1.676: C25.- 85.52,28.87 85.23,29.07 85.43,28.87 84.63,28.87 84.31,28.87 | 84.31,28.87 84.03,28.87 | 84.31,28.87 JP2.2
  Bottom 1.778: 88.23,31.18 88.23,31.07 | 88.23,31.18 C25.- | CON6.BACK 88.23,38.36 88.23,31.18 | CON6.L1 78.83,30.52 78.83,36.47 80.83,38.47 86.98,38.47 87.01,38.5
  pour Bottom (no thermals): 58.83,32.07 62.03,32.07 62.03,28.87 58.83,28.87
ERROR_X  (via drill 0.4)
  Top 0.2: CON4.T1 57.63,36.27 v58.23,35.67 | 38.75,46.81 39.09,46.81 v39.43,46.47 | v41.43,48.87 CON5.R4 | CON1.T4 38.63,36.27 v38.76,33.89
  Top 0.4: CON5.R4 41.43,49.47
  Top 0.406: 38.75,46.47 38.75,46.81 | 38.75,46.47 CON5.B4 | CON1.T4 38.75,36.47 38.75,46.47 | CON5.R4 46.68,49.47 57.63,38.52 57.63,36.67 57.58,36.62 57.63,36.57 CON4.T1
  Bottom 0.2: v58.23,35.67 58.23,35.27 59.83,33.67 61.3,33.67 61.72,33.25 61.72,32.71 61.7,32.69 | 61.7,32.69 61.67,32.66 | 61.7,32.69 IC1.23 | v39.43,46.47 40.63,46.47 41.43,47.27 v41.43,48.87 | U1.11 40.05,27.85 39.83,28.07 37.35,28 37.35,27.99 36.23,26.87 35.23,26.87 34.63,27.47 34.63,29.47 34.83,29.67 34.84,29.66 | 34.84,29.66 34.77,29.6 | 34.84,29.66 36.78,31.26 37.63,33.27 v38.76,33.89
ERROR_Y  (via drill 0.4)
  Top 0.2: CON4.B1 v56.96,25.95 | v39.43,12.47 40.63,12.47 CON3.R1
  Top 0.406: CON3.R1 47.03,11.47 57.68,22.12 57.68,24.32 57.53,24.47 | 57.53,24.47 57.48,24.52 | 57.53,24.47 CON4.B1
  Bottom 0.2: IC1.9 57.31,28.68 v56.96,25.95 | U4.11 42.2,6.24 42.43,6.47 42.43,12.67 | 42.43,12.67 42.03,13.07 | 42.43,12.67 42.43,12.68 41.85,13.27 40.12,13.27 v39.43,12.47
ERROR_Z  (via drill 0.4)
  Top 0.2: CON4.T2 59.63,34.87 v59.83,34.67 | CON5.L4 30.23,49.47 v30.83,48.87 | v41.63,50.87 CON5.R3 | 13.53,36.27 11.73,34.07 11.23,34.07 10.63,33.67 v10.63,32.27
  Top 0.406: CON5.R3 47.33,51.47 59.63,39.17 59.63,36.57 59.58,36.52 CON4.T2 | CON5.L4 25.63,49.47 13.53,37.37 13.53,36.27 13.88,35.92 13.88,36.27 13.63,36.52 CON2.T4
  Bottom 0.2: v59.83,34.67 61.03,34.67 61.43,34.27 62.03,34.27 62.23,34.07 62.23,32.67 62.2,32.7 IC1.24 | v30.83,48.87 32.83,46.87 32.83,46.27 33.43,45.67 41.23,45.67 42.23,46.67 42.23,50.27 v41.63,50.87 | U3.11 14.83,27.87 14.83,26.76 14.54,26.47 10.23,26.47 9.63,27.27 9.63,31.27 v10.63,32.27
MISO  (via drill 0.4)
  Top 0.2: CON1.L2 30.43,31.47 | 30.43,31.47 31.03,32.07 31.03,32.13 31.46,32.96 31.46,33.56 32.8,34.9 34.07,34.9 34.43,35.06 34.63,35.27 CON1.T2 | 30.43,31.47 31.23,31.47 31.58,30.99 32.03,29.76 35.64,29.76 v36.03,29.27 36.23,29.27 36.83,28.67 36.83,25.07 36.63,24.87 CON1.B3 | U5.9 32.6,50.3 33.03,49.87 33.03,48.27 34.63,46.67 CON5.B2 | v38.43,10.27 38.83,10.67 38.83,12.07 37.63,13.27 37.23,13.27 36.63,13.87 CON3.T3 | CON2.R2 15.03,31.47 v14.83,31.07 | CON1.R1 40.63,32.47 39.83,32.47 39.43,32.07 39.43,31.97 v39.4,32.14 | v54.42,34.54 54.23,33.87 CON4.L1 54.71,33.39 55.21,33.39 56.13,32.47 56.23,32.47 56.43,32.27 56.44,32.28 v56.62,32.28 v56.63,32.27
  Top 0.4: CON1.B3 CON3.T3 | CON1.R1 CON4.L1
  Top 0.406: 34.48,36.47 34.48,36.27 | CON1.T2 34.48,36.47 | CON5.B2 34.48,46.47 34.48,36.47 | CON1.L2 29.53,31.57 29.43,31.47 CON2.R2
  Bottom 0.2: v36.03,29.27 37.66,30.9 39.67,30.87 39.43,31.67 | IC1.16 56.76,32.14 v56.63,32.27 | X3.1 61.63,36.87 56.07,36.83 54.63,35.47 54.63,34.75 v54.42,34.54 | v38.43,10.27 39.23,10.27 39.23,10.07 40.23,9.27 41.23,9.27 41.21,9.29 U4.8 | 40.2,30.9 U1.8 39.63,30.87 39.43,31.67 | 39.43,31.67 v39.4,32.14 | U3.8 16.43,30.87 | U3.8 | v14.83,31.07 16.23,31.07 U3.8
MOSI  (via drill 0.4)
  Top 0.2: CON1.T3 36.43,36.27 36.63,36.07 36.63,33.47 35.63,32.67 35.56,32.65 35.26,31.89 35.51,31.46 35.71,31.19 36.28,31.19 36.52,30.9 38.01,30.9 v38.52,30.07 38.44,30.34 38.99,29.45 40.6,29.41 41.06,29.16 41.35,29.52 41.05,29.47 CON1.R3 | 54.63,29.57 55.13,29.57 v56.43,30.87 | U5.5 33.8,52.91 33.81,52.88 33.8,52.88 33.79,52.87 34.15,52.51 34.15,48.03 34.41,47.77 35.24,47.77 35.43,47.58 35.43,46.67 35.83,46.67 36.23,47.07 36.63,47.07 | 36.63,47.07 36.23,46.87 | CON5.B3 36.63,47.07 | CON1.L3 31.23,29.47 31.23,27.3 31.6,26.93 32.35,26.93 32.89,27.47 34.33,27.47 | 34.33,27.47 34.9,27.93 35.53,27.93 35.84,28.05 35.95,28 v35.96,27.97 | 34.33,27.47 34.33,25.06 CON1.B2 | v39.43,8.87 38.83,9.47 38.03,9.47 37.63,9.87 37.63,10.47 38.23,11.07 38.23,11.87 37.23,12.87 35.43,12.87 34.63,13.67 CON3.T2 | v14.83,29.87 14.83,29.67 15.23,29.27 16.43,29.27 CON2.R3
  Top 0.4: CON1.B2 CON3.T2
  Top 0.406: 36.63,36.37 CON1.T3 CON5.B3 | 16.63,29.37 16.53,29.27 | CON2.R3 16.63,29.37 | CON1.L3 16.73,29.47 16.63,29.37 | CON1.R3 42.48,29.47 42.53,29.42 54.18,29.42 54.48,29.72 54.63,29.57 CON4.L3
  Bottom 0.2: 37.33,29.75 36.63,28.6 v35.96,27.97 | 37.33,29.75 37.44,29.88 | IC1.15 58.06,31.64 58.03,31.67 57.23,31.67 v56.43,30.87 v56.43,30.88 55.96,31.47 55.96,32.79 56.44,33.23 56.45,33.24 56.46,33.24 56.46,34.8 56.4,34.86 56.35,34.97 56.04,35.2 55.7,35.2 55.63,35.27 55.63,35.87 56.23,36.47 60.43,36.47 X2.1 | U4.9 39.63,8.27 v39.43,8.87 | 37.33,29.75 37.35,29.75 37.5,29.97 38.4,30.03 v38.52,30.07 38.49,30.24 38.97,29.9 U1.9 | U3.9 14.88,29.92 v14.83,29.87
N$1
  Bottom 0.2: 55.02,29.86 55.01,29.85 LED1.A | R2.2 55.02,29.86 | 55.02,29.86 55.03,29.87
N$2
  Bottom 0.2: U$2.R4 67.07,27.71 67.03,27.67 65.06,29.64 IC1.30
N$3  (via drill 0.4)
  Top 0.2: C3.1 34.83,28.87 33.83,27.87 32.43,27.87 32.31,27.75 v32.12,27.75
  Bottom 0.2: U1.21 31.79,26.83 v32.12,27.75
N$4  (via drill 0.4)
  Top 0.2: C4.1 33.15,28.95 v32.31,28.96
  Bottom 0.2: U1.23 30.42,28.86 30.43,28.87 v32.31,28.96
N$5  (via drill 0.4)
  Top 0.4: C4.2 32.81,30.45 v32.43,30.87
  Bottom 0.4: v32.43,30.87 31.83,29.87 30.43,29.87 30.42,29.88 U1.24
N$6
  Bottom 0.2: IC1.31 64.76,29.14 66.03,27.27 66.03,25.87 67.41,25.08 | 67.41,25.08 67.43,25.07 | 67.41,25.08 U$2.R5
N$7
  Bottom 0.2: R2.1 55.42,26.26 55.89,26.86 55.87,29.51 56.63,30.07 56.83,30.07 57.43,30.67 58.23,30.67 58.2,30.64 IC1.13
N$8  (via drill 0.4)
  Top 0.2: U5.2 32.85,54.85 34.83,52.87 34.83,48.67 34.98,48.52 | 34.98,48.52 35.03,48.47 | v34.96,48.52 34.98,48.52
  Bottom 0.2: U2.12 35.2,49.3 v34.96,48.52
N$9  (via drill 0.4)
  Top 0.2: U5.16 36.66,52.91 36.24,52.72 36.25,49.24 36.43,48.84 36.81,48.26 37.35,48.26 37.78,48.03 | 37.78,48.03 37.81,48 | v37.78,48.11 37.78,48.03
  Bottom 0.2: U2.10 36.8,48.9 v37.78,48.11
N$10  (via drill 0.4)
  Top 0.2: 37.49,50.3 37.48,50.31 | 37.49,50.3 U5.12 | 37.49,50.3 37.5,50.29 36.84,50.29 36.71,50.16 36.71,49.29 37.07,48.89 38.13,48.88 38.61,48.6 38.7,48.6 38.83,48.47 38.89,48.53 v39,48.53
  Bottom 0.2: U2.9 37.6,48.9 v39,48.53
N$11
  Top 0.2: R6.2 35.84,26.48 35.83,26.47 35.81,26.49 R4.1
N$12  (via drill 0.4)
  Top 0.4: C8.1 9.33,27.67 v7.33,27.67
  Bottom 0.4: v7.33,27.67 7.43,27.47 7.23,27.67 7.23,26.87 5.83,26.87 U3.21
N$13  (via drill 0.4)
  Top 0.4: C9.1 8.63,28.67 8.43,28.87 v7.43,28.87
  Bottom 0.4: U3.23 7.4,28.9 v7.43,28.87
N$14  (via drill 0.4)
  Top 0.4: 33.85,33.87 33.83,33.87 | L1.2 34.69,33.87 33.85,33.87 | 33.85,33.87 C2.2 | 33.85,33.87 32.83,33.87 32.43,33.47 v32.43,33.13 32.43,33.07
  Bottom 0.4: U1.27 32.29,32.93 v32.43,33.13
N$15
  Bottom 0.2: 67.41,30.25 67.43,30.27 | 67.41,30.25 U$2.R3 | IC1.29 67.3,30.14 67.41,30.25
N$16  (via drill 0.4)
  Top 0.4: C9.2 7.98,30.32 v7.63,29.97
  Bottom 0.4: U3.24 5.78,29.92 5.83,29.97 v7.63,29.97
N$23  (via drill 0.4)
  Top 0.4: C13.1 34.63,5.67 v34.33,5.45
  Bottom 0.2: U4.21 31.88,5.22 32.22,4.97 34.02,4.97 34.43,5.27 v34.33,5.45
N$24  (via drill 0.4)
  Top 0.4: C14.1 32.63,5.67 32.83,5.87 v32.23,5.87
  Bottom 0.4: U4.23 31.85,7.25 32.23,6.87 v32.23,5.87
N$25
  Bottom 0.2: IC1.27 64.7,31.14 66.23,32.67 66.23,34.47 67.43,35.67 67.41,35.69 U$2.R1
N$26  (via drill 0.4)
  Top 0.4: L3.2 32.63,11.47 C12.2 32.28,11.32 v32.23,11.27
  Bottom 0.4: U4.27 30.38,11.32 30.43,11.27 v32.23,11.27
N$27  (via drill 0.4)
  Top 0.4: 32.83,7.67 C14.2 v32.23,8.27
  Bottom 0.4: U4.24 v32.23,8.27
N$50  (via drill 0.4)
  Top 0.2: v35.92,48.11 35.83,49.07 35.63,49.27 35.63,53.07 36.77,54.2 U5.18
  Bottom 0.2: 34.4,47.1 34.43,47.07 34.3,46.94 34.3,46.92 34.6,46.62 R1.1 | U2.13 34.34,49.57 34.3,49.53 | v35.92,48.11 35.08,47.27 34.43,47.27
  Bottom 0.3: U2.13 34.4,49.04 34.03,48.67 34.03,47.67 34.43,47.27 34.4,47.24 34.4,47.1
N$53
  Top 0.2: U5.11 37.62,49.66 37.64,49.68 U6.4
N$54  (via drill 0.4)
  Top 0.4: C7.2 7.63,33.27 v8.43,33.27 9.03,33.27 L2.2
  Bottom 0.4: U3.27 8.13,32.97 v8.43,33.27
N$56
  Bottom 0.2: IC1.28 64.8,30.64 66.63,32.47 66.83,32.47 67.41,33.05 | 67.41,33.05 67.43,33.07 | 67.41,33.05 U$2.R2
N$57  (via drill 0.4)
  Top 0.2: v58.51,26.74 58.75,27.03 60.03,28.47 60.03,28.87 60.23,29.07 60.08,29.22 X1.1
  Bottom 0.2: 59.22,28 59.2,28.02 IC1.7 | 59.22,28 59.2,27.98 | 59.22,28 59.22,27.46 v58.51,26.74 58.44,24.54 59.24,24.38 59.18,24.32 C16.2
N$58  (via drill 0.4)
  Top 0.2: v58.12,27.65 59.03,28.47 59.03,30.07 58.83,30.27 58.23,30.27 58.23,31.52 X1.3
  Bottom 0.2: IC1.8 58.66,28.04 58.63,28.07 v58.12,27.65 58.12,27.52 57.63,27.25 57.73,25.24 57.68,25.19 57.43,24.86 57.44,24.73 C17.1
N$61
  Bottom 1.676: CON6.R1 97.26,34.47 92.45,34.47 JP1.1
N$62
  Bottom 1.676: JP1.2 92.03,31.63 92.03,31.67 97.16,31.67 CON6.R2
N$63
  Bottom 1.676: 97.36,29.27 97.43,29.27 | 97.36,29.27 CON6.R3 | JP1.3 92.33,29.27 97.36,29.27
N$64
  Bottom 1.676: 97.42,26.47 97.43,26.47 | 97.42,26.47 CON6.R4 | JP1.4 92.11,26.47 97.42,26.47
N$65
  Bottom 1.676: CON6.R5 97.23,23.94 97.23,23.67 92.37,23.67 JP1.5
SCK  (via drill 0.4)
  Top 0.2: CON1.L1 30.43,33.47 | 32.43,36.27 32.63,36.07 | CON1.B1 31.63,24.47 v31.19,24.07 | v29.44,34.91 29.43,33.67 CON1.L1 | v64.87,36.52 64.87,35.51 64.43,35.07 62.51,35.06 61.83,34.38 60.64,34.39 60.14,33.89 60.05,33.89 60.03,33.87 59.23,33.87 58.7,34.4 58.7,34.77 58.41,35 57.47,35 57.23,34.86 | CON5.B1 v31.63,46.47 | 37.05,54.85 U5.19 37.45,54.85 37.43,54.87 36.63,54.87 35.63,53.87 34.83,53.87 33.43,55.27 33.43,56.47 33.83,56.87 v39.64,56.87 | 32.43,36.27 32.43,35.28 30.57,33.42 29.5,33.42 | 29.5,33.42 29.55,33.47 CON1.L1 | 29.5,33.42 29.44,33.36 | 32.43,36.27 v31.2,36.79 | 32.43,36.27 CON1.T1 | CON3.T1 32.63,13.67 33.23,13.07 34.43,12.27 36.83,12.27 v37.36,11.23 | 38.43,32.27 v38.41,32.26 v38.42,32.27 38.43,32.27 | CON1.R2 41.43,31.27 39.23,31.27 38.63,31.87 38.43,32.27 | 54.63,31.67 54.74,31.56 57.29,31.56 57.31,31.58 57.31,33.23 v57.43,33.07 57.23,33.27 57.23,34.86 | 57.23,34.86 57.23,34.87
  Top 0.4: 16.73,33.42 14.58,33.42 v14.23,32.67 | CON4.L2 54.63,31.67 41.83,31.67 CON1.R2
  Top 0.406: 32.58,36.47 32.58,36.17 | CON1.T1 32.58,36.47 | CON5.B1 32.58,46.47 32.58,36.47 | CON1.B1 32.53,24.37 32.63,24.27 CON3.T1 | CON2.R1 16.68,33.47 16.73,33.42 16.78,33.47 CON1.L1
  Bottom 0.2: 41.23,32.87 41.17,32.93 U1.6 | 41.23,32.87 41.03,32.87 41.05,32.89 U1.6 | v31.19,24.07 29.23,24.07 29.03,24.27 29.03,34.67 29.23,34.87 v29.44,34.91 | IC1.17 57.76,32.74 v57.43,33.07 | v64.87,36.52 X4.1 | v39.64,56.87 38.43,57.27 31.23,57.27 29.74,56.22 29.74,49.67 30.03,49.27 30.03,48.57 30.72,47.88 30.72,47.78 31.63,46.87 v31.63,46.47 | v31.2,36.79 31.22,36.8 31.23,36.87 31.43,37.07 35.43,37.07 35.63,37.27 36.83,37.27 37.03,37.07 40.23,37.07 41.03,36.27 41.03,35.07 40.74,34.78 40.1,34.78 39.63,34.27 39.43,33.47 38.83,32.87 | U4.6 40.88,11.32 40.83,11.27 40.63,11.47 37.61,11.46 37.38,11.23 v37.36,11.23 | 38.83,32.87 v38.41,32.26 | 41.23,32.87 U1.6 | 38.83,32.87 41.23,32.87
  Bottom 0.4: v14.23,32.67 14.53,33.07 16.23,33.07 16.33,32.97 U3.6
SS_ACCEL  (via drill 0.4)
  Top 0.2: CON4.T3 v61.63,35.27 | U6.2 39.42,51.86 39.83,52.27 40.23,52.27 41.43,53.47 | U5.3 31.23,54.2 30.91,54.47 30.91,56.37 31.89,57.3 38.84,57.3 39.28,57.74 39.9,57.74 40.51,57.13 40.51,56.35 41.15,56.35 41.43,56.07 41.43,53.67 CON5.R2 41.43,53.47 | 41.43,53.47 41.03,53.87
  Top 0.406: CON4.T3 61.63,39.52 47.63,53.52 41.58,53.52 41.53,53.47 | 41.53,53.47 41.48,53.42 | CON5.R2 41.53,53.47
  Bottom 0.2: v61.63,35.27 61.63,35.07 61.83,34.87 62.52,34.87 62.76,34.63 62.76,32.18 IC1.25
SS_X  (via drill 0.4)
  Top 0.2: v38.62,27.23 39.63,27.47 CON1.R4 | v56.58,29.07 56.48,27.85 56.23,27.47 CON4.L4 | v38.62,27.23 38.39,27.23 | 38.62,27.26 38.63,27.27 | 38.62,27.26 v38.62,27.23 | R6.1 37.84,26.48 38.62,27.26
  Top 0.406: CON1.R4 41.63,27.42 41.68,27.47 CON4.L4
  Bottom 0.2: U1.7 42.21,31.91 42.33,31.79 42.33,26.17 42.03,25.87 40.25,25.87 39.71,26.41 39.71,26.59 39.39,26.91 38.63,27.27 v38.62,27.23 | IC1.10 56.7,29.14 v56.58,29.07
SS_Y  (via drill 0.4)
  Top 0.2: v62.23,24.67 61.83,24.67 CON4.B3 | CON3.R3 v39.1,7.23 39.1,7.6 37.54,9.16 R3.2
  Top 0.406: CON3.R3 48.43,7.47 61.68,20.72 61.68,24.32 61.78,24.42 61.73,24.47 CON4.B3
  Bottom 0.2: IC1.1 62.66,28.04 63.23,27.47 63.23,25.67 v62.23,24.67 | U4.7 39.8,10.3 39.23,11.07 38.23,11.07 37.63,10.47 37.63,9.87 38.63,9.27 38.63,7.67 v39.1,7.23
SS_Z  (via drill 0.4)
  Top 0.2: 63.43,24.47 CON4.B4 v64.43,24.47 | 29.83,5.52 29.83,5.47 31.23,4.47 37.83,4.47 38.23,4.87 38.3,5.63 39.02,6.34 39.65,6.3 40.23,5.67 40.23,5.47 40.43,5.27 41.23,5.27 41.43,5.47 CON3.R4 | R5.1 11.62,26.27 11.63,26.27 11.63,26.87 10.83,26.87
  Top 0.4: CON2.B1 7.63,26.27 10.83,26.27 10.83,26.87 v10.83,27.27
  Top 0.406: CON4.B4 63.63,19.92 49.13,5.42 42.03,5.42 41.98,5.37 41.88,5.47 CON3.R4 | CON2.B1 7.63,21.82 23.93,5.52 29.83,5.52 29.78,5.47 CON3.L4
  Bottom 0.2: IC1.32 63.46,28.64 63.63,28.47 63.63,25.27 v64.43,24.47
  Bottom 0.4: U3.7 14.91,31.95 13.83,31.67 13.63,31.47 11.03,31.47 v10.83,27.27
VCC  (via drill 0.4)
  Top 0.2: 61.83,26.67 C22.1 61.83,27.07 v61.97,26.83 | U5.20 38.04,55.5 38.33,55.21 38.33,50.76 38.57,50.52 39.41,50.52 40.07,49.86 U6.5 | R4.2 33.43,26.47 33.31,26.59 v33.31,26.74 | R5.2 13.92,26.36 14.33,26.57
  Top 0.4: L2.1 11.63,32.47 v11.83,32.27 | v61.97,26.83 C22.1 IC3.1 61.03,29.42 61.03,30.27 60.83,30.47 59.43,30.47 59.15,30.65 59.15,33.05 58.03,34.27 57.92,34.47 v57.99,34.3 | CON4.C1 54.83,36.47 | 41.63,46.57 41.63,46.85 40.14,48.34 40.14,49.69 40.13,49.68 U6.5 | 37.6,55.5 37.63,55.47 | U5.20 37.6,55.5 | C18.1 36.9,56 37.6,55.5 | v30.83,14.47 CON3.C1 29.83,14.47 32.03,12.27 33.43,12.27 33.63,12.07 33.63,11.87 34.03,11.47 35.83,11.47 v36.11,11.07 L3.1 | L3.1 | 37.24,31.86 37.63,31.47 38.23,31.47 38.83,30.87 39.63,30.67 C5.2 | 37.24,31.86 37.23,31.87 37.43,32.07 37.21,32.99 37.76,33.23 38.95,33.06 39,33.06 39.9,33.53 40.11,35.55 v40.23,35.67 | 37.24,31.86 C1.2 37.33,31.77 | 37.33,31.77 37.43,31.87 | 37.08,31.65 37.21,31.65 37.33,31.77 | C11.2 35.68,5.42 35.83,5.27 v35.83,5.47 36.23,5.87 C15.2 | L3.1 36.05,10.49 34.97,9.41 R3.1
  Top 0.406: 41.63,46.57 CON5.C3 CON1.C4 | CON1.C4 41.58,36.47 41.48,36.57 | CON1.C4 CON4.C1 | CON3.C1 29.63,24.27 29.73,24.37 CON1.C2 16.88,24.47 16.83,24.52 16.78,24.47 CON2.C3
  Top 0.5: 12.43,28.67 12.38,28.62 C6.2 | 13.43,28.62 C6.2 | 13.43,28.62 C10.2 | C6.2 12.43,28.67 | CON2.C3 14.33,26.57 13.43,27.27 13.43,28.62 | 13.43,28.62 13.43,28.67 | 12.43,28.67 11.83,28.67 11.03,28.97 11.03,31.07 11.83,31.87 v11.83,32.27 | C1.2 37.01,31.68 | 37.21,32.99 L1.1 | CON1.C4 41.43,36.47 40.43,35.47 | 40.43,35.47 40.43,35.27 | v40.23,35.67 40.43,35.47 | 36.97,31.83 36.94,31.57 37.08,31.65 v36.15,31.9 | v33.31,26.74 32.64,26.37 29.73,24.57 29.73,24.37 | 54.83,36.47 55.68,35.68 v56.5,35.68
  Bottom 0.2: C23.1 57.4,34.5 v57.99,34.3 57.83,34.47 59.2,33.1 IC1.18 | IC1.4 60.7,27.6 60.81,27.4 61.01,27.4 61.85,26.65 | 61.85,26.65 C24.1 61.98,26.47 62.03,26.47 62.03,26.08 61.61,25.45 59.76,25.45 59.6,25.65 59.35,26.1 59.35,26.75 59.69,27.29 IC1.6 | 61.85,26.65 61.85,26.49 v61.97,26.83 | U4.4 39.23,13.27 38.23,12.27 37.43,12.27 36.23,11.07 v36.11,11.07
  Bottom 0.3: 29.03,2.67 28.99,14.04
  Bottom 0.4: U3.4 14.38,34.02 12.63,32.27 v11.83,32.27 | 29.03,2.67 29.84,1.86 U$4.1 35.63,1.87 35.63,0.87 68.66,0.87 CON6.FRONT | 28.99,14.04 29.43,14.47 v30.83,14.47 | v35.83,5.47 36.03,5.67 36.03,6.87 35.23,7.67 35.23,10.27 36.03,11.07 v36.11,11.07
  Bottom 0.5: U1.4 39.38,35.72 39.43,35.67 v40.23,35.67 | v33.31,26.74 33.27,27.57 33.59,28.54 34.03,29.87 v36.15,31.9 | C23.1 57.27,34.47 57.23,34.47 57.23,34.67 v56.5,35.68
  Bottom 1.27: C26.2 82.23,26.65 82.23,26.47 84.03,26.47
  Bottom 1.676: C25.+ 87.7,26.47 84.45,26.47 | 84.45,26.47 JP2.1 | 84.45,26.47 84.03,26.47
  Bottom 1.778: C25.+ 88.03,26.27 88.03,20.24 CON6.FRONT
VCC2.5  (via drill 0.4)
  Top 0.3: CON5.C4 41.63,57.27 v41.43,57.07
  Top 0.4: IC3.5 61.73,33.37 61.63,33.47 | CON4.C4 66.17,36.47 66.17,35.61 65.05,34.54 62.84,34.54 62.35,33.97 62.03,33.87 61.63,33.47 | 61.63,33.47 61.6,33.45 C21.+ | U5.1 31.69,55.55 31.7,55.56 31.83,55.83 v32.23,56.27
  Top 0.406: CON5.C4 47.41,58.47 66.69,39.19 66.69,36.65 66.63,36.59 CON4.C4
  Bottom 0.2: R1.2 36.35,46.6 36.43,46.68 36.03,47.14
  Bottom 0.3: v32.23,56.27 32.63,56.67 38.83,56.67 39.43,56.07 40.03,56.07 41.03,57.07 v41.43,57.07 42.23,56.27 42.23,53.47 42.14,53.38 C19.1 | U2.11 36,49.1 36.63,48.47 36.63,47.07 | R1.2 36.23,46.67 36.63,47.07 | 36.63,47.07 38.43,47.07 39.03,47.67 39.83,47.67 40.43,48.27 40.43,53.38
  Bottom 0.4: U2.19 32.19,53.51 31.63,54.07 31.23,54.07 31.17,54.13 C20.1 31.09,54.13 31.03,54.07 31.03,56.07 31.23,56.27 v32.23,56.27 | C19.1 40.43,53.38 40.29,53.38 40.2,53.47 39.3,53.47 39.26,53.51 U2.3

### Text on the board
Top: Top Copper
Bottom: Bottom Copper
tPlace: # | # | # | 1 | 2 | - | RST | 5V | o | o | + | IN | OUT | o | Top Silkscreen
bPlace: B | L | T | R | NewAE | 2 | IMU | F | Bottom Silkscreen
tStop: Top Soldermask
bStop: Bottom Soldermask
Drill_legend: Copyright Colin O'Flynn, NewAE. <coflynn@newae.com> | Note: Board checked to 6mil space/trace | Locations with closer spacing are not important, | as they are electrically isolated. If shorts appear at those | it does not affect board. | Drill legend | Date: 7/05/2006 21:09:35 | 1.0160 mm / 40.000 mil | 0.6000 mm / 23.622 mil | 0.5000 mm / 19.685 mil | 0.4000 mm / 15.748 mil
